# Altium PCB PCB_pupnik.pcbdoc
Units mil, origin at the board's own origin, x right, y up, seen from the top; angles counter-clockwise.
Board outline 4571.99 x 3535.82 mil, 4 copper layers (Top Layer, Inner1, Inner2, Bottom Layer); 78 components, 82 nets, 346 pads, 314 vias.
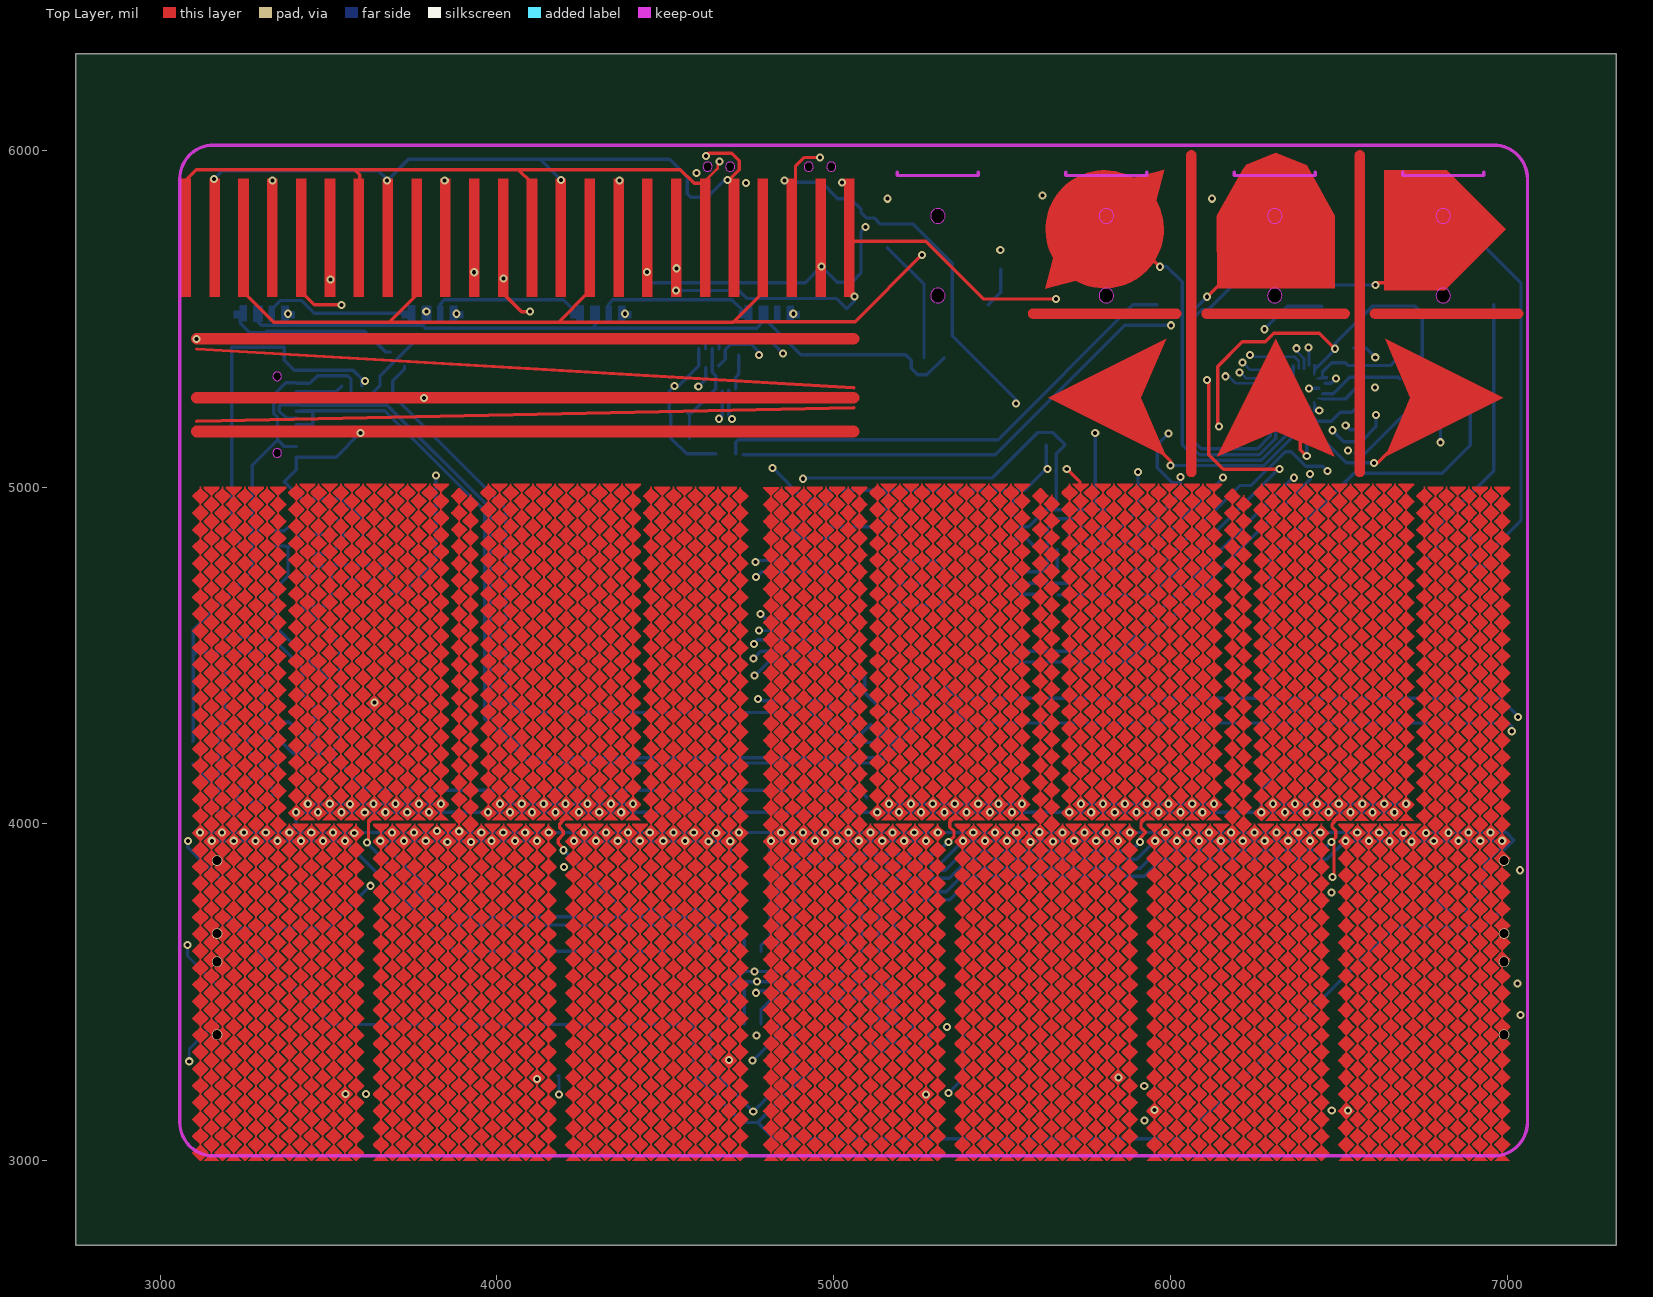
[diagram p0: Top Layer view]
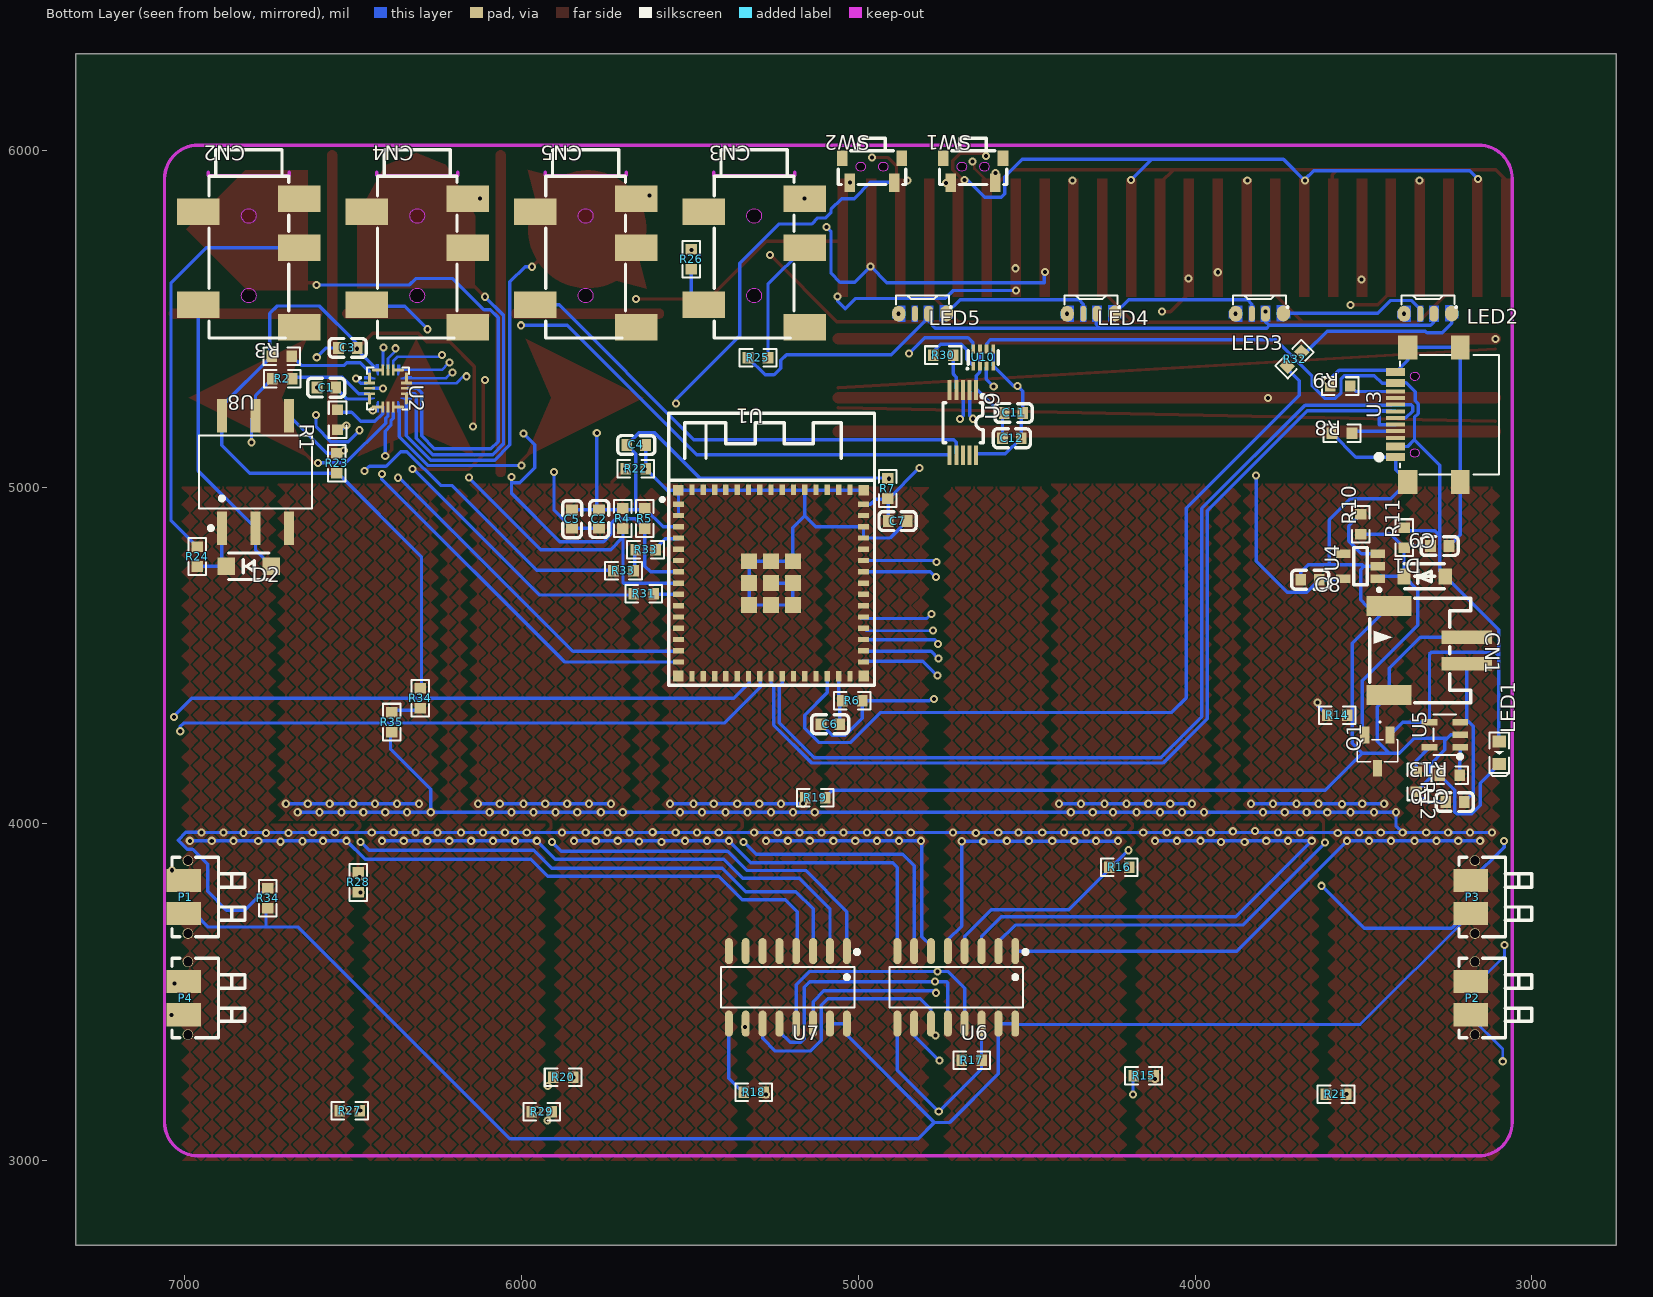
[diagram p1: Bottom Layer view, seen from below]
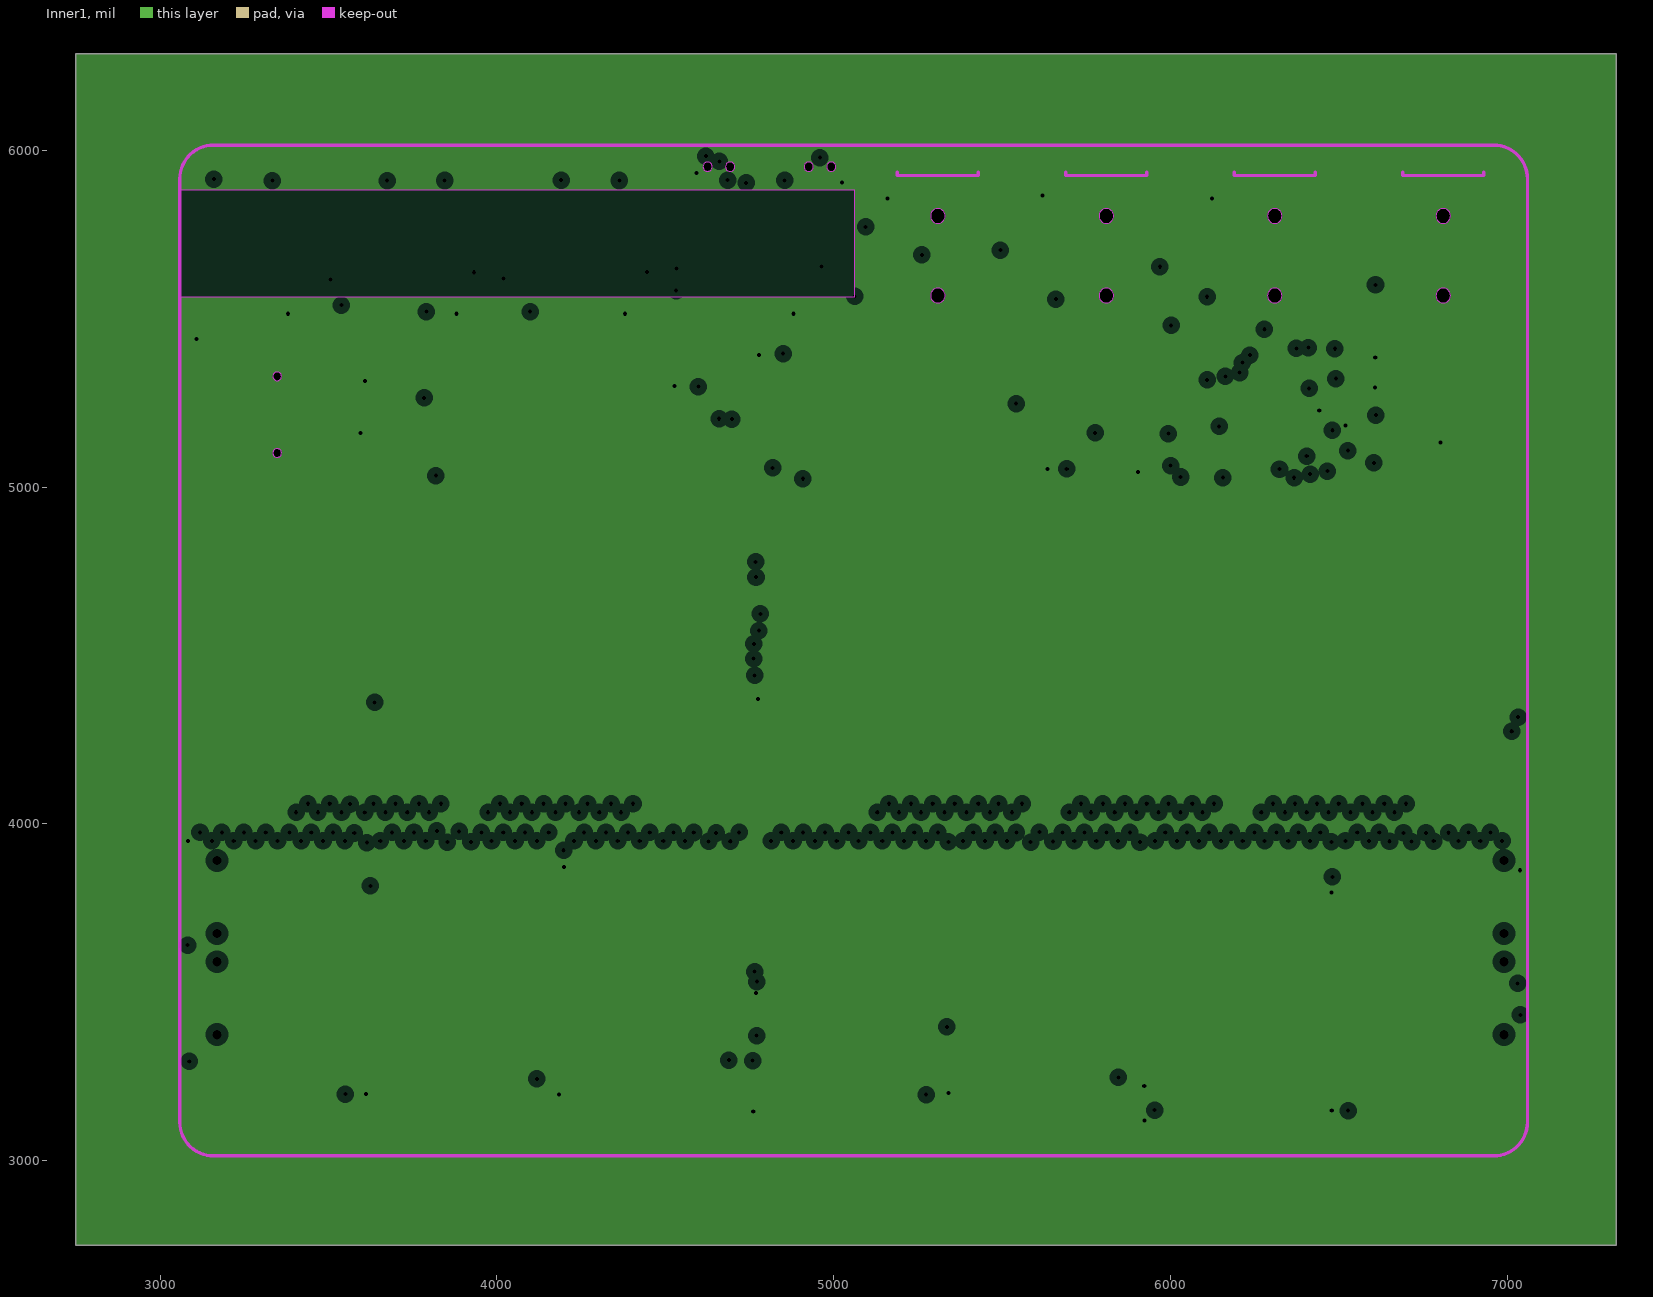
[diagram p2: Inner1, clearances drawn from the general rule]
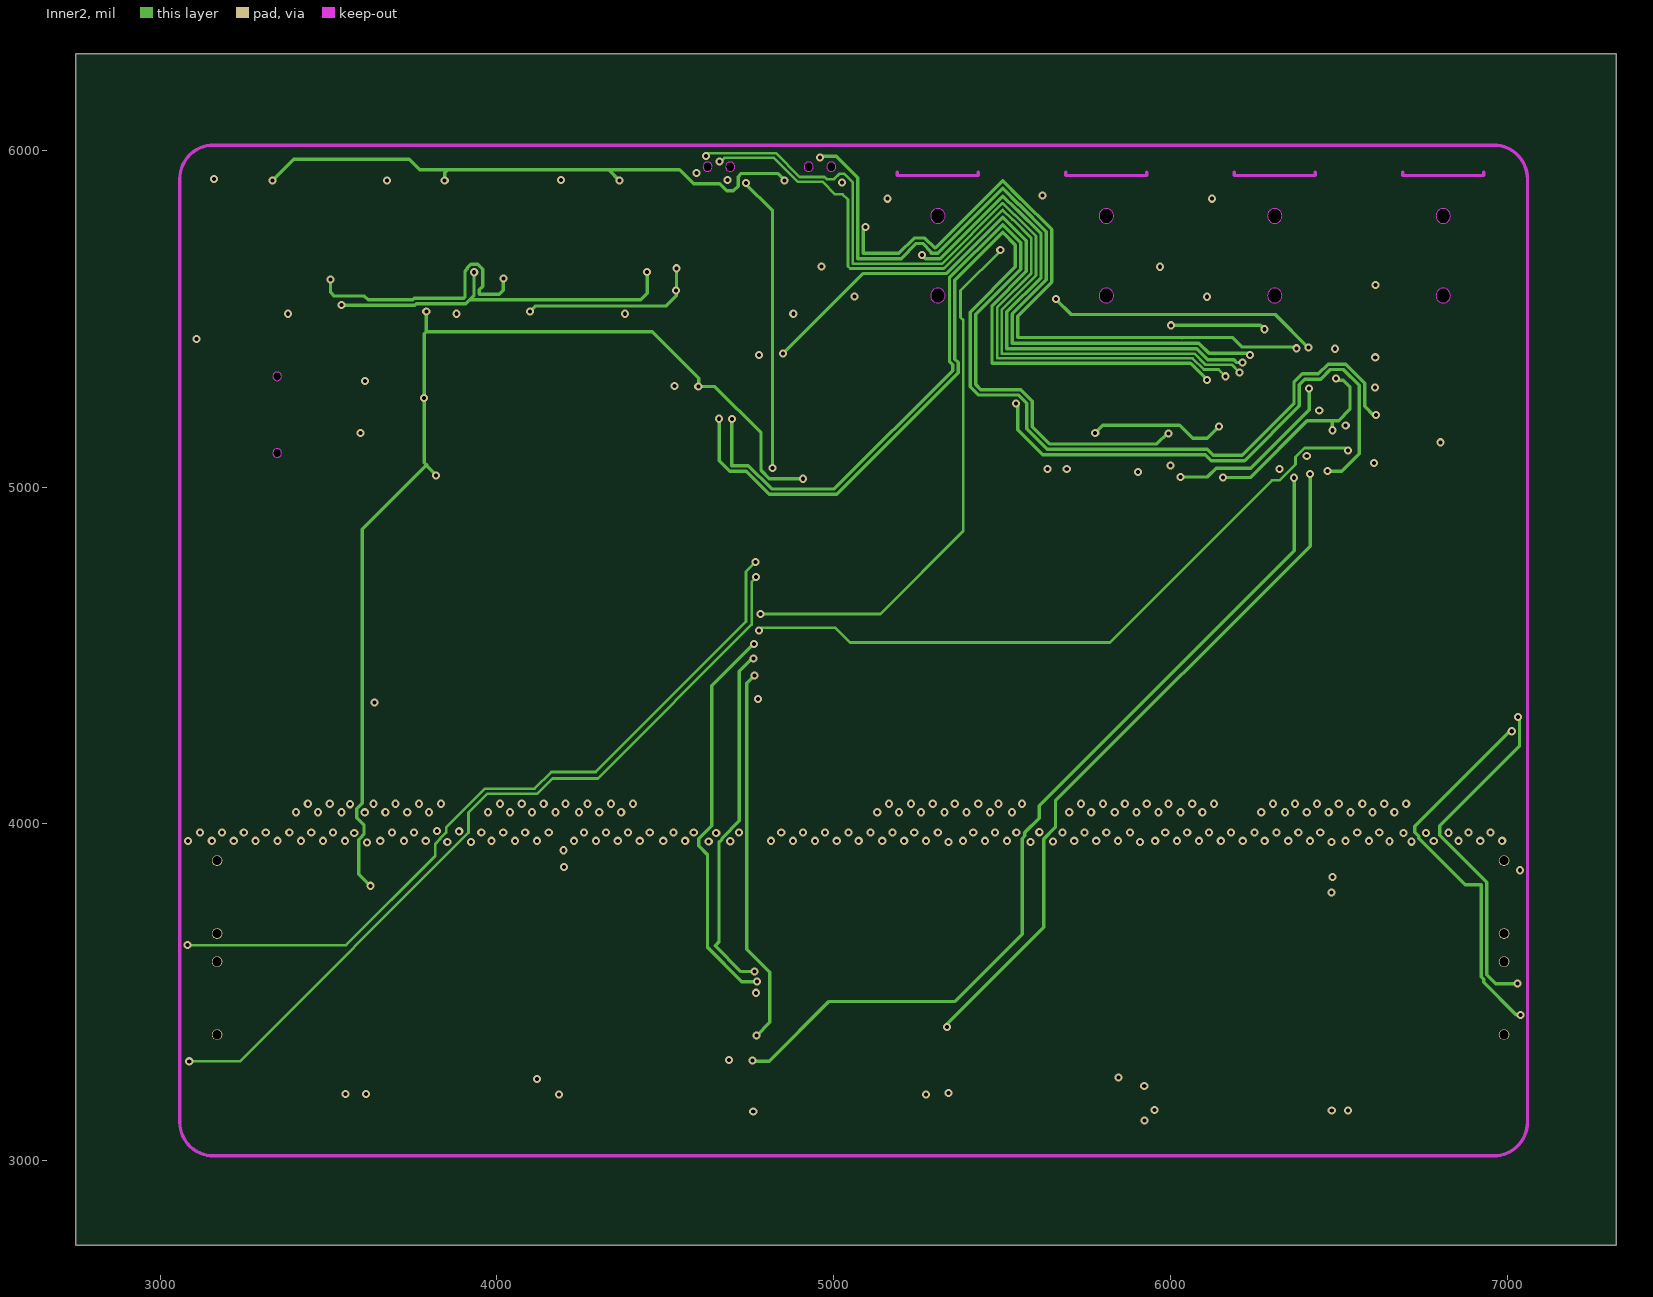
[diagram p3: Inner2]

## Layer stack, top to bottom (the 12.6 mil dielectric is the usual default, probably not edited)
Top Layer: signal copper (thickness not stored)
Dielectric: dielectric 12.6, FR-4, Dk 4.8
Inner1: plane copper (thickness not stored)
Dielectric: dielectric 12.6, FR-4, Dk 4.8
Inner2: signal copper (thickness not stored)
Dielectric: dielectric 12.6, FR-4, Dk 4.8
Bottom Layer: signal copper (thickness not stored)

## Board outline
7321.99,2750 2750,2750 2750,6285.82 7321.99,6285.82

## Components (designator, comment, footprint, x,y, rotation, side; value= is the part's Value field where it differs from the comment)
C1 "0.1u" C0603 6578.64,5294.85 r180 bottom
C2 "0.1u" C0603 5768.64,4904.85 r270 bottom
C3 "1u" C0603 6514.76,5412.85 r180 bottom
C4 "10u" C0603 5658.64,5124.85 r0 bottom
C5 "10u" C0603 5848.64,4904.85 r90 bottom
C6 "1u" C0603 5082.64,4295.85 r180 bottom
C7 "1u" C0603 4882.64,4898.85 r180 bottom
C8 "10u" C0603 3658.64,4724.85 r0 bottom
C9 "10u" C0603 3273.64,4824.85 r180 bottom
C10 "10u" C0603 3228.64,4064.85 r180 bottom
C11 "10u" C0603 4538.76,5219.85 r0 bottom
C12 "0.1u" C0603 4543.76,5144.85 r0 bottom
CN1 "BAT" CONN-SMD_P2.00_S2B-PH-SM4-TB-LF-SN 3308.64,4514.85 r270 bottom
CN2 "MIDI IN" AUDIO-SMD_PJ-327A5JJ 6808.64,5664.85 r180 bottom
CN3 "MIDI OUT" AUDIO-SMD_PJ-327A5JJ 5308.64,5664.85 r180 bottom
CN4 "CV" AUDIO-SMD_PJ-327A5JJ 6308.64,5664.85 r180 bottom
CN5 "GT" AUDIO-SMD_PJ-327A5JJ 5808.64,5664.85 r180 bottom
D1 "SM4007PL" SOD-123F_L2.8-W1.8-LS3.7-RD 3318.64,4734.85 r180 bottom
D2 "1N4148W" SOD-123FL_L2.6-W1.6-LS3.4-RD 6808.64,4764.85 r0 bottom
LED1 "LED-0603_R" LED0603_RED 3097.11,4211.38 r270 bottom
LED2 "SK6812SIDE-A-RVS" LED-SMD_4P-L4.0-W1.6-L 3308.64,5514.85 r0 bottom
LED3 "SK6812SIDE-A-RVS" LED-SMD_4P-L4.0-W1.6-L 3808.64,5514.85 r0 bottom
LED4 "SK6812SIDE-A-RVS" LED-SMD_4P-L4.0-W1.6-L 4308.64,5514.85 r0 bottom
LED5 "SK6812SIDE-A-RVS" LED-SMD_4P-L4.0-W1.6-L 4808.64,5514.85 r0 bottom
P1 "PogoPIN 2PIN 2.54mm" "POGOPIN 2PIN 2.5MM" 6898.64,3664.85 r270 bottom
P2 "PogoPIN 2PIN 2.54mm" "POGOPIN 2PIN 2.5MM" 3078.64,3364.85 r270 bottom
P3 "PogoPIN 2PIN 2.54mm" "POGOPIN 2PIN 2.5MM" 3078.64,3664.85 r270 bottom
P4 "PogoPIN 2PIN 2.54mm" "POGOPIN 2PIN 2.5MM" 6898.64,3364.85 r270 bottom
Q1 "DMG3415U-7" SOT-23-3_L2.9-W1.6-P1.90-LS2.8-BR-CW 3458.64,4214.85 r90 bottom
R1 "75k" R0603 6545.3,5199.51 r90 bottom
R2 "10k" R0603 6709.3,5321.51 r180 bottom
R3 "10k" R0603 6710.64,5388.85 r180 bottom
R4 "10k" R0603 5697.98,4906.51 r270 bottom
R5 "10k" R0603 5632.98,4906.51 r270 bottom
R6 "1M" R0603 5017.32,4365.85 r0 bottom
R7 "5.1k" R0603 4911.98,4995.51 r270 bottom
R8 "5.1k" R0603 3563.64,5159.85 r180 bottom
R9 "5.1k" R0603 3568.64,5299.85 r180 bottom
R10 "100k" R0603 3508.64,4889.85 r90 bottom
R11 "100k" R0603 3378.64,4849.85 r90 bottom
R12 "5.1k" R0603 3343.64,4124.85 r270 bottom
R13 "5.1k" R0603 3243.64,4144.85 r180 bottom
R14 "100K" R0603 3577.96,4322.85 r0 bottom
R15 "100K" R0603 4152.64,3252.85 r180 bottom
R16 "100K" R0603 4224.96,3871.85 r0 bottom
R17 "100K" R0603 4662.96,3298.85 r0 bottom
R18 "100K" R0603 5309.64,3203.85 r180 bottom
R19 "100K" R0603 5126.96,4077.85 r0 bottom
R20 "100K" R0603 5875.64,3247.85 r180 bottom
R21 "100K" R0603 3581.64,3197.85 r180 bottom
R22 "100K" R0603 5659.96,5053.85 r0 bottom
R23 "470" R0603 6546.98,5070.51 r270 bottom
R24 "220" R0603 6961.98,4793.51 r270 bottom
R25 "33" R0603 5297.32,5383.85 r0 bottom
R26 "10" R0603 5495.64,5675.85 r90 bottom
R27 "100K" R0603 6509.32,3148.85 r0 bottom
R28 "100K" R0603 6484.3,3826.51 r90 bottom
R29 "100K" R0603 5939.32,3145.85 r0 bottom
R30 "5.1k" R0603 4747.64,5391.85 r180 bottom
R31 "10k" R0603 5636.64,4682.85 r180 bottom
R32 "Res_0603" R0603 3704.64,5379.85 r315 bottom
R33 "Res_0603" R0603 5630.84,4813.97 r180 bottom
R33 "Res_0603" R0603 5696.48,4751.9 r180 bottom
R34 "Res_0603" R0603 6299.21,4372.78 r270 bottom
R34 "Res_0603" R0603 6752.83,3779.44 r90 bottom
R35 "Res_0603" R0603 6384.35,4302.22 r270 bottom
SW1 "RST" SW-SMD_L4.7-W3.5-P3.35-EH 4658.64,5939.85 r180 bottom
SW2 "BOOT" SW-SMD_L4.7-W3.5-P3.35-EH 4958.64,5939.85 r180 bottom
U1 "ESP32-S3-MINI-1-N8" BULETM-SMD_ESP32-S3-MINI-1-N8 5258.64,4714.85 r180 bottom
U2 "MPR121QR2" QFN-20_L3.0-W3.0-P0.40-BL 6395.64,5292.85 r270 bottom
U3 "GT-USB-9047A" USB-C-SMD_GT-USB-9047A 3308.64,5214.85 r90 bottom
U4 "AP2112K-3.3TRG1" SOT-25-5_L2.9-W1.6-P0.95-LS2.8-BL 3508.64,4764.85 r90 bottom
U5 "MCP73831T-2ACI/OT" SOT-23-5_L3.0-W1.7-P0.95-LS2.8-BL 3258.64,4264.85 r90 bottom
U6 "MCP3008-I/SL" SOIC-16_L9.9-W3.9-P1.27-LS6.0-BL 4708.64,3514.85 r0 bottom
U7 "MCP3008-I/SL" SOIC-16_L9.9-W3.9-P1.27-LS6.0-BL 5208.64,3514.85 r0 bottom
U8 "H11L1VSMT&amp;R" SMD-6_L8.6-W6.4-P2.54-LS9.4-BL 6788.64,5044.85 r180 bottom
U9 "MCP4728-E/UN" MSOP-10_L3.0-W3.0-P0.50-LS5.0-TL 4688.87,5191 r270 bottom
U10 "LM66200DRLR" SOT-583-8_L2.1-W1.2-P0.50-LS1.6-BL 4628.64,5384.85 r180 bottom

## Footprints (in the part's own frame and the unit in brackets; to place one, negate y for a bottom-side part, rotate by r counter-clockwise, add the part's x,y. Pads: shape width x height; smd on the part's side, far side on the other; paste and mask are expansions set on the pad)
AUDIO-SMD_PJ-327A5JJ [mm]
  rect 3.2x2 smd: 1(3.8,4.85) 2(-3.8,3.85) 3(3.8,1.15) 4(-3.8,-3.15) 5(3.8,-4.85)
  Board Outline Layer lines w0.254: 3.048,6.604 -3.048,6.604 ; 3.048,6.604 -3.048,6.604 ; 3.048,6.604 3.048,6.858 3.048,6.604 ; -3.048,6.604 -3.048,6.858 -3.048,6.604
  Multi-Layer board cut-out: -0.55,3.55 -0.496,3.789 -0.343,3.98 -0.123,4.086 0.122,4.086 0.343,3.98 0.495,3.789 0.55,3.55 0.55,3.55 0.495,3.311 0.343,3.12 0.122,3.014 -0.123,3.014 -0.343,3.12 -0.496,3.311 -0.55,3.55
  Multi-Layer board cut-out: -0.55,-2.45 -0.496,-2.211 -0.343,-2.02 -0.123,-1.914 0.122,-1.914 0.343,-2.02 0.495,-2.211 0.55,-2.45 0.55,-2.45 0.495,-2.689 0.343,-2.88 0.122,-2.986 -0.123,-2.986 -0.343,-2.88 -0.496,-2.689 -0.55,-2.45
  Multi-Layer keep-out region: -0.55,3.55 -0.496,3.789 -0.343,3.98 -0.123,4.086 0.122,4.086 0.343,3.98 0.495,3.789 0.55,3.55 0.55,3.55 0.495,3.311 0.343,3.12 0.122,3.014 -0.123,3.014 -0.343,3.12 -0.496,3.311 -0.55,3.55
  Multi-Layer keep-out region: -0.55,-2.45 -0.496,-2.211 -0.343,-2.02 -0.123,-1.914 0.122,-1.914 0.343,-2.02 0.495,-2.211 0.55,-2.45 0.55,-2.45 0.495,-2.689 0.343,-2.88 0.122,-2.986 -0.123,-2.986 -0.343,-2.88 -0.496,-2.689 -0.55,-2.45
  silkscreen extent -3,-5.65 3,8.55
BULETM-SMD_ESP32-S3-MINI-1-N8 [mm]
  rect 0.8x0.4 smd: 1(-6.975,5.95) 2(-6.975,5.1) 3(-6.975,4.25) 4(-6.975,3.4) 5(-6.975,2.55) 6(-6.975,1.7) 7(-6.975,0.85) 8(-6.975,0) 9(-6.975,-0.85) 10(-6.975,-1.7) 11(-6.975,-2.55) 12(-6.975,-3.4) 13(-6.975,-4.25) 14(-6.975,-5.1) 15(-6.975,-5.95) 31(6.975,-5.95) 32(6.975,-5.1) 33(6.975,-4.25) 34(6.975,-3.4) 35(6.975,-2.55) 36(6.975,-1.7) 37(6.975,-0.85) 38(6.975,0) 39(6.975,0.85) 40(6.975,1.7) 41(6.975,2.55) 42(6.975,3.4) 43(6.975,4.25) 44(6.975,5.1) 45(6.975,5.95)
  rect 0.4x0.8 smd: 16(-5.95,-7.025) 17(-5.1,-7.025) 18(-4.25,-7.025) 19(-3.4,-7.025) 20(-2.55,-7.025) 21(-1.7,-7.025) 22(-0.85,-7.025) 23(0,-7.025) 24(0.85,-7.025) 25(1.7,-7.025) 26(2.55,-7.025) 27(3.4,-7.025) 28(4.25,-7.025) 29(5.1,-7.025) 30(5.95,-7.025) 46(5.95,7.025) 47(5.1,7.025) 48(4.25,7.025) 49(3.4,7.025) 50(2.55,7.025) 51(1.7,7.025) 52(0.85,7.025) 53(0,7.025) 54(-0.85,7.025) 55(-1.7,7.025) 56(-2.55,7.025) 57(-3.4,7.025) 58(-4.25,7.025) 59(-5.1,7.025) 60(-5.95,7.025)
  rect 0.8x0.8 smd: 61(7,7) 62(-7,-7) 63(7,-7) GND(-7,7)
  rect 1.2x1.2 smd: 64(-1.65,1.65) 65(0,1.65) 66(1.65,1.65) 67(-1.65,0) 68(0,0) 69(1.65,0) 70(-1.65,-1.65) 71(0,-1.65) 72(1.65,-1.65)
  silkscreen extent -8.34,-7.7 7.8,12.8
C0603 [mm]
  rect 0.8x0.9 smd: 1(-0.7,0) 2(0.7,0)
  silkscreen extent -1.41,-0.71 1.39,0.72
CONN-SMD_P2.00_S2B-PH-SM4-TB-LF-SN [mm]
  rect 1x3.8 smd: 1(-1,2.925) 2(1,2.925)
  rect 1.5x3.4 smd: 3(3.35,-2.925) 4(-3.35,-2.925)
  silkscreen extent -3.95,-4.37 3.95,3.22
LED0603_RED [mm]
  rect 0.9x1 smd: 1(-0.85,0) 2(0.85,0)
  silkscreen extent -1.54,-0.73 1.75,0.73
LED-SMD_4P-L4.0-W1.6-L [mm]
  oval 1x1.2 smd: 1(-1.8,-0.012) 4(1.8,0.013)
  oval 0.7x1.2 smd: 2(-0.45,0.013)
  oval 0.45x1.2 smd: 3(0.575,0.013)
  Top Layer region: 1.3,0.612 1.3,-0.588 1.85,-0.587 1.85,-0.188 2.3,-0.188 2.3,0.362 1.85,0.362 1.85,0.612
  Top Layer region: 0.35,-0.588 0.8,-0.588 0.8,0.612 0.35,0.612
  Top Layer region: -0.8,0.613 -0.8,-0.587 -0.1,-0.587 -0.1,0.613
  Top Layer region: -1.3,0.588 -1.3,-0.612 -1.85,-0.612 -1.85,-0.212 -2.3,-0.212 -2.3,0.338 -1.85,0.338 -1.85,0.588
  silkscreen extent -2.2,-1.36 2,-0.41
MSOP-10_L3.0-W3.0-P0.50-LS5.0-TL [mil]
  rect 59.05x12 smd: 1(-96.5,39.37) 2(-96.5,19.68) 3(-96.5,0) 4(-96.5,-19.69) 5(-96.5,-39.37) 6(96.5,-39.37) 7(96.5,-19.69) 8(96.5,0) 9(96.5,19.68) 10(96.5,39.37)
  silkscreen extent -84,-59 59,64
"POGOPIN 2PIN 2.5MM" [mm]
  rect 1.75x2.6 smd: 1(-4.25,-2.6) 2(-1.75,-2.6)
  round 0.8 hole 0.7: 3(-5.75,-2.3) 4(-0.25,-2.3)
  silkscreen extent -6,-3.5 0,2
QFN-20_L3.0-W3.0-P0.40-BL [mm]
  oval 0.825x0.224 smd: 1(-0.8,-1.388) 5(0.8,-1.388) 11(0.8,1.388) 15(-0.8,1.388)
  rect 0.2x0.825 smd: 2(-0.4,-1.388) 3(0,-1.388) 4(0.4,-1.388) 12(0.4,1.388) 13(0,1.388) 14(-0.4,1.388)
  oval 0.224x0.825 smd: 6(1.388,-0.8) 10(1.388,0.8) 16(-1.387,0.8) 20(-1.388,-0.8)
  rect 0.825x0.2 smd: 7(1.388,-0.4) 8(1.388,0) 9(1.388,0.4) 17(-1.387,0.4) 18(-1.387,0) 19(-1.387,-0.4)
  Top Layer region: 0.688,-1.8 0.688,-0.975 0.8,-0.975 0.912,-1.388 0.912,-1.8
  Top Layer region: -1.8,-0.688 -0.975,-0.688 -0.975,-0.8 -1.388,-0.912 -1.8,-0.912
  Top Layer region: -0.688,1.8 -0.688,0.975 -0.8,0.975 -0.912,1.388 -0.912,1.8
  Top Layer region: 1.8,0.688 0.975,0.688 0.975,0.8 1.388,0.912 1.8,0.912
  Top Layer region: 1.8,-0.688 0.975,-0.688 0.975,-0.8 1.388,-0.912 1.8,-0.912
  Top Layer region: 0.688,1.8 0.688,0.975 0.8,0.975 0.912,1.388 0.912,1.8
  Top Layer region: -1.8,0.688 -0.975,0.688 -0.975,0.8 -1.387,0.912 -1.8,0.912
  Top Layer region: -0.688,-1.8 -0.688,-0.975 -0.8,-0.975 -0.912,-1.388 -0.912,-1.8
  silkscreen extent -1.58,-2.18 1.58,1.58
R0603 [mil]
  rect 31.75x34.02 smd: 1(-29.66,0) 2(29.66,0)
  silkscreen extent -55,-26 55,26
SMD-6_L8.6-W6.4-P2.54-LS9.4-BL [mil]
  rect 29.76x99.37 smd: 1(-100,-166.81) 2(0,-166.81) 3(100,-166.81) 4(100,166.81) 5(0,166.81) 6(-100,166.81)
  silkscreen extent -168,-173 168,108
SOD-123F_L2.8-W1.8-LS3.7-RD [mm]
  rect 1x1.2 smd: 1(-1.55,0) 2(1.55,0)
  silkscreen extent -1.52,-0.93 1.49,0.95
SOD-123FL_L2.6-W1.6-LS3.4-RD [mm]
  rect 1.3x1.3 smd: 1(1.7,0) 2(-1.7,0)
  silkscreen extent -1.5,-1 1.5,1
SOIC-16_L9.9-W3.9-P1.27-LS6.0-BL [mil]
  oval 23.7x77.6 smd: 1(-175,-107.7) 2(-125,-107.7) 3(-75,-107.7) 4(-25,-107.7) 5(25,-107.7) 6(75,-107.7) 7(125,-107.7) 8(175,-107.7) 9(175,107.7) 10(125,107.7) 11(75,107.7) 12(25,107.7) 13(-25,107.7) 14(-75,107.7) 15(-125,107.7) 16(-175,107.7)
  silkscreen extent -211,-111 198,60
SOT-23-3_L2.9-W1.6-P1.90-LS2.8-BR-CW [mm]
  rect 1.25x0.7 smd: 1(1.25,-0.95) 2(-1.25,0) 3(1.25,0.95)
  silkscreen extent -0.76,-1.52 2.28,1.52
SOT-23-5_L3.0-W1.7-P0.95-LS2.8-BL [mm]
  rect 0.49x1.157 smd: 1(-0.95,-1.154) 2(0,-1.154) 3(0.95,-1.154)
  rect 0.49x1.175 smd: 4(0.95,1.154) 5(-0.95,1.154)
  silkscreen extent -1.8,-1.29 1.53,0.85
SOT-25-5_L2.9-W1.6-P0.95-LS2.8-BL [mil]
  rect 24.5x43.5 smd: 1(-37.39,-51.18) 2(-0.03,-51.18) 3(37.39,-51.18) 4(37.39,51.18) 5(-37.39,51.18)
  silkscreen extent -75,-60 56,20
SOT-583-8_L2.1-W1.2-P0.50-LS1.6-BL [mm]
  rect 0.28x0.68 smd: 1(-0.75,-0.64) 2(-0.25,-0.64) 3(0.25,-0.64) 4(0.75,-0.64) 5(0.75,0.64) 6(0.25,0.64) 7(-0.25,0.64) 8(-0.75,0.64)
  silkscreen extent -1.27,-0.93 1.14,0.51
SW-SMD_L4.7-W3.5-P3.35-EH [mm]
  rect 0.8x1.4 smd: 1(-1.675,-0.917) 2(1.675,-0.917)
  rect 0.8x1.2 smd: 3(-2.25,0.917) 4(2.25,0.917)
  Multi-Layer board cut-out: -1.2,0.282 -1.165,0.434 -1.068,0.556 -0.928,0.624 -0.772,0.624 -0.632,0.556 -0.535,0.434 -0.5,0.282 -0.5,0.282 -0.535,0.131 -0.632,0.009 -0.772,-0.059 -0.928,-0.059 -1.068,0.009 -1.165,0.131 -1.2,0.282
  Multi-Layer board cut-out: 0.5,0.282 0.535,0.434 0.632,0.556 0.772,0.624 0.928,0.624 1.068,0.556 1.165,0.434 1.2,0.282 1.2,0.282 1.165,0.131 1.068,0.009 0.928,-0.059 0.772,-0.059 0.632,0.009 0.535,0.131 0.5,0.282
  Multi-Layer keep-out region: -1.2,0.282 -1.165,0.434 -1.068,0.556 -0.928,0.624 -0.772,0.624 -0.632,0.556 -0.535,0.434 -0.5,0.282 -0.5,0.282 -0.535,0.131 -0.632,0.009 -0.772,-0.059 -0.928,-0.059 -1.068,0.009 -1.165,0.131 -1.2,0.282
  Multi-Layer keep-out region: 0.5,0.282 0.535,0.434 0.632,0.556 0.772,0.624 0.928,0.624 1.068,0.556 1.165,0.434 1.2,0.282 1.2,0.282 1.165,0.131 1.068,0.009 0.928,-0.059 0.772,-0.059 0.632,0.009 0.535,0.131 0.5,0.282
  silkscreen extent -2.54,-1.07 2.54,2.43
USB-C-SMD_GT-USB-9047A [mm]
  rect 1.8x1.45 smd: 12(-5.07,1.524) 13(5.07,1.524)
  rect 1.8x1.4 smd: 14(-5.07,-2.436) 15(5.07,-2.436)
  rect 0.6x1.45 smd: A1B12(-3.2,2.437) A4B9(-2.4,2.437) A9B4(2.4,2.437) A12B1(3.2,2.437)
  rect 0.3x1.45 smd: A5(-1.25,2.437) A6(-0.25,2.437) A7(0.25,2.437) A8(1.25,2.437) B5(1.75,2.437) B6(0.75,2.437) B7(-0.75,2.437) B8(-1.75,2.437)
  Multi-Layer board cut-out: 2.89,1.319 3.031,1.286 3.144,1.196 3.207,1.066 3.207,0.921 3.144,0.791 3.031,0.701 2.89,0.669 2.89,0.669 2.749,0.701 2.636,0.791 2.573,0.921 2.573,1.066 2.636,1.196 2.749,1.286 2.89,1.319
  Multi-Layer board cut-out: -2.89,1.318 -2.749,1.286 -2.636,1.196 -2.573,1.065 -2.573,0.921 -2.636,0.791 -2.749,0.7 -2.89,0.668 -2.89,0.668 -3.031,0.7 -3.144,0.791 -3.207,0.921 -3.207,1.065 -3.144,1.196 -3.031,1.286 -2.89,1.318
  Multi-Layer keep-out region: 2.89,1.319 3.031,1.286 3.144,1.196 3.207,1.066 3.207,0.921 3.144,0.791 3.031,0.701 2.89,0.669 2.89,0.669 2.749,0.701 2.636,0.791 2.573,0.921 2.573,1.066 2.636,1.196 2.749,1.286 2.89,1.319
  Multi-Layer keep-out region: -2.89,1.318 -2.749,1.286 -2.636,1.196 -2.573,1.065 -2.573,0.921 -2.636,0.791 -2.749,0.7 -2.89,0.668 -2.89,0.668 -3.031,0.7 -3.144,0.791 -3.207,0.921 -3.207,1.065 -3.144,1.196 -3.031,1.286 -2.89,1.318
  silkscreen extent -4.5,-5.36 4.5,3.89

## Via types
v1: diameter 24.41, hole 12.2, Top Layer to Bottom Layer, 180 vias
v2: diameter 24, hole 12, Top Layer to Bottom Layer, 134 vias

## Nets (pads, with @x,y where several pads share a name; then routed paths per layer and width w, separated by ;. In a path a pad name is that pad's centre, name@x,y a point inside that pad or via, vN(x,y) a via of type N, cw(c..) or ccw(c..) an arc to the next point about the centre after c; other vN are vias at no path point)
3V3: C2.1 C3.2 C4.2 C5.2 C8.1 LED2.2 LED3.2 LED4.2 LED5.2 P1.2 P3.2 R3.1 R4.1 R5.1 R7.1 R23.2 R25.2 R34.1 U1.3 U2.20 U4.5 U6.15 U6.16 U7.15 U7.16 U8.6 U10.3 | length 18170.9
  Top Layer w10: v2(6143.62,5179.75) 6138.89,5184.49 6138.89,5357.78 6212.16,5431.05 6280.09,5431.05 6305.28,5456.24 6441.14,5456.24 v2(6486.93,5410.44)
  Top Layer w35: 3108.64,5264.85 v2(3783.64,5264.85) 5058.64,5264.85
  Inner2 w10: v2(3624.18,3816.46) 3589.93,3850.7 3589.93,3953.33 3595.22,3958.62 3595.22,3959.28 3605.22,3969.28 3605.22,3997.08 3583.43,4018.86 3583.43,4045.4 3599.71,4061.69 3599.71,4874.35 3790.21,5064.84 ; v2(3790.21,5520.76) 3790.21,5461.17 ; 3791.64,5066.28 3790.21,5064.84 ; v2@3818.64,5036.29 3790.21,5064.72 3790.21,5064.84 ; v2(4597.56,5298.34) v2@4599.13,5298.34 ; v2@4599.13,5297.9 v2@4599.13,5298.34 ; v2(4908.29,5024.65) 4808.31,5024.65 4783.88,5049.08 4783.88,5161.27 4646.82,5298.34 v2@4599.13,5298.34 ; v2(5775.74,5160.92) 5798.38,5183.56 6026.08,5183.56 6065.01,5144.64 6108.52,5144.64 v2(6143.62,5179.75) ; 3790.21,5064.84 3783.64,5071.41 v2(3783.64,5264.85) 3783.64,5454.6 3790.21,5461.17 ; 3790.21,5461.17 4460.77,5461.17 4599.13,5322.81 v2@4599.13,5298.34
  Bottom Layer w8: P3.2@3185.96,3728.55 3509.96,3404.55 U6.16@4535.77,3404.55
  Bottom Layer w10: P3.2@3182.46,3729.4 3199.2,3729.4 3238.64,3689.95 3497.67,3689.95 v2@3622.99,3815.27 ; LED2.2 3290.93,5489.74 3300.93,5479.74 3779.75,5479.74 ; U4.5 3562.43,4724.85 C8.1 3668.45,4687.48 3726.28,4687.48 3818.64,4779.83 v2(3818.64,5034) ; LED3.2 3790.93,5490.91 3779.75,5479.74 ; LED4.2 4293.64,5511.64 4293.64,5482.85 4282.64,5471.85 ; U6.16 U6.15 4583.64,3258.85 4728.64,3113.85 4773.64,3113.85 ; v2(4597.56,5298.34) 4619.79,5320.57 U10.3@4619.79,5354.77 ; LED5.2 LED5.2@4790.93,5503.56 ; R7.1 4913.66,5026.85 5470.64,5026.85 5605.64,5161.85 5649.2,5161.85 C4.2 5660.33,5098.98 5660.33,4932.41 ; U7.15 U7.16 5033.64,3373.85 4773.64,3113.85 ; R25.2 5275.98,5332.85 5249.64,5332.85 5229.64,5352.85 5229.64,5375.85 5212.64,5392.85 4901.64,5392.85 LED5.2@4790.93,5503.56 ; U1.3 5578.99,4882.18 R5.1 5636.74,4932.41 5660.33,4932.41 ; C2.1@5769.63,4938.05 5775.74,4944.15 v2(5775.74,5160.92) ; C5.2 C2.1 5660.33,4932.41 ; R34.1@6296.18,4401.17 6296.18,4793.68 R23.2@6542.71,5040.21 ; U2.20 6487.2,5407.54 C3.2 ; C3.2@6488.65,5415.98 6488.65,5426.67 6599.32,5537.34 6724.49,5537.34 6746.63,5515.2 R3.1@6746.63,5386.21 ; R23.2 6805.64,5040.85 6888.64,5123.85 U8.6 6888.64,5240.51 R3.1 ; R34.1@6757.41,3747.38 6757.41,3696.5 6757.92,3695.99 ; P1.2@6985.01,3733.41 6968.28,3733.41 6928.83,3693.96 6661.63,3693.96 6033.62,3065.95 4821.54,3065.95 4773.64,3113.85 ; 3779.75,5479.74 3787.64,5471.85 4282.64,5471.85 ; 4282.64,5471.85 4770.64,5471.85 4790.93,5492.14 LED5.2@4790.93,5503.56
$1N143: R1.2 U2.7 | length 178.1
  Bottom Layer w10: U2.7 6411.39,5217.76 6434.3,5194.85 6476.64,5194.85 6503.64,5221.85 6537.98,5221.85 R1.2
$1N157: R2.2 U2.4 | length 251.3
  Bottom Layer w10: U2.4@6450.27,5277.34 6482.13,5277.34 6530.64,5325.85 6675.3,5325.85 R2.2
$1N175: R3.2 U2.1 | length 274.1
  Bottom Layer w10: U2.1 6450.27,5341.48 6477.64,5368.85 6517.64,5368.85 6525.64,5360.85 6652.98,5360.85 R3.2
$1N193: C1.2 U2.5 | length 114.7
  Bottom Layer w10: U2.5 6517.57,5261.34 C1.2
$1N354: C6.2 R6.2 U1.29 | length 150.3
  Bottom Layer w10: C6.2 5055.08,4357.75 R6.2 5057.85,4376.72 U1.29
$1N512: C9.1 D1.1 Q1.3 R10.1 R11.1 U4.1 | length 951.8
  Bottom Layer w10: C9.1 3373.98,4824.85 R11.1 ; U4.1 3450.07,4734.85 D1.1 ; Q1.3 3503.64,4271.65 3503.64,4424.85 3338.64,4589.85 3338.64,4693.83 D1.1 ; R10.1 3418.64,4860.19 R11.1 ; R11.1 3379.66,4819.17 D1.1
$1N704: C10.2 CN1.2 U5.3 | length 457.4
  Bottom Layer w10: CN1.2 3193.48,4309.69 3186.04,4302.25 ; C10.2 3173.64,4092.29 3173.64,4289.85 3186.04,4302.25 ; U5.3 3186.04,4302.25
$1N1108: LED2.3 LED3.1 | length 446.5
  Bottom Layer w10: LED2.3 3331.28,5527.49 3357.64,5553.85 3419.64,5553.85 3458.15,5515.34 LED3.1
$1N1109: LED3.3 LED4.1 | length 457.2
  Bottom Layer w10: LED3.3 3831.28,5542.97 3844.16,5555.85 4197.27,5555.85 LED4.1
$1N1133: LED4.3 LED5.1 | length 457.2
  Bottom Layer w10: LED4.3 4331.28,5542.97 4344.16,5555.85 4697.27,5555.85 LED5.1
$1N1275: CN2.4 D2.2 U8.2 | length 865.7
  Bottom Layer w10: D2.2 6788.64,4811.78 U8.2 6958.24,5047.64 CN2.4
$1N1289: CN2.3 R24.1 | length 1238.1
  Bottom Layer w10: CN2.3 6934.37,5710.12 7039.64,5604.85 7039.64,4900.83 R24.1
$1N1451: C11.2 C12.2 U9.1 U10.2 U10.7 | length 312.8
  Bottom Layer w10: C12.2 4571.32,5214.85 C11.2 4577.77,5219.85 4649.27,5291.35 4649.27,5330.47 4638.48,5341.26 U10.2 U10.7
$1N1517: CN4.4 U9.6 | length 1910.6
  Inner2 w10: v2(6001.23,5480.11) 6266.34,5480.11 v2(6278.04,5468.41)
  Bottom Layer w10: U9.6@4730.54,5095.88 5478.85,5095.88 5863.09,5480.11 v2(6001.23,5480.11) ; v2(6278.04,5468.41) 6345.97,5536.34 CN4.4@6449.01,5536.34
$1N1518: CN5.4 U9.7 | length 1453.4
  Bottom Layer w10: U9.7@4708.33,5098.35 4708.33,5132.88 4716.3,5140.85 5487.64,5140.85 5887.62,5540.83 CN5.4
$1N1636: R8.2 U3.A5 | length 131.8
  Bottom Layer w10: U3.A5 3528.19,5165.64 R8.2
$1N1637: R9.2 U3.B5 | length 141.1
  Bottom Layer w10: U3.B5@3404.57,5283.75 3522.89,5283.75 R9.2
$1N1644: R10.2 U4.3 | length 195.9
  Bottom Layer w10: U4.3 3506.03,4802.24 3543.64,4839.85 3543.64,4884.51 R10.2
$1N1651: R13.2 U5.1 | length 82.6
  Bottom Layer w10: U5.1 R13.2@3213.94,4144.85
$1N1656: R12.1 U5.5 | length 89.3
  Bottom Layer w10: U5.5 3343.64,4187.87 R12.1
$1N1659: LED1.2 R13.1 | length 362.4
  Bottom Layer w10: LED1.2 3153.64,4121.39 3153.64,4054.85 3178.64,4029.85 3223.64,4029.85 3228.64,4034.85 3228.64,4100.19 R13.1
$1N1720: D2.1 R24.2 U8.1 | length 205.4
  Bottom Layer w10: U8.1 6888.64,4777.92 D2.1 6960.98,4764.85 R24.2
$1N1727: CN3.4 R26.1 | length 120.9
  Bottom Layer w10: CN3.4 5495.64,5578.23 R26.1
$1N1728: CN3.3 R25.1 | length 371.3
  Bottom Layer w10: CN3.3 5267.66,5601.5 R25.1
$1N1745: R30.2 U9.4 | length 104.5
  Bottom Layer w10: U9.4@4708.33,5291.35 4708.33,5325.88 4717.98,5335.53 R30.2
$1N1760: R31.1 U10.8 | length 3476.2
  Top Layer w10: v2@6108.16,5320.05 6113.12,5315.09 6113.12,5096.29 6156.43,5052.98 v2(6322.72,5052.98)
  Inner2 w10: v2@4850.38,5397.71 5086.33,5633.67 5333.29,5633.67 5501.1,5801.47 5570.88,5731.69 5570.88,5639.92 5469.51,5538.56 5469.51,5366.93 6058.68,5366.93 v2(6107.59,5318.02)
  Bottom Layer w10: U10.8@4659.06,5409.93 4659.06,5428.31 4673.75,5443 4802.55,5443 v2(4849.36,5396.19) ; R31.1@5666.2,4679.47 5945.63,4679.47 v2@6318.65,5052.49
A_SIG: R29.2 U7.2 | length 1539
  Bottom Layer w10: U7.2 5083.64,3747.85 5174.64,3838.85 5342.64,3838.85 5398.64,3894.85 5898.64,3894.85 v1(5953.64,3949.85) v1(6413.64,3949.85)
  other v1: 6018.64,3949.85 6083.64,3949.85 6148.64,3949.85 6213.64,3949.85 6278.64,3949.85 6348.64,3949.85
  other v2: 5951.8,3150.39
ADC-CS-0: U1.14 U6.10 | length 3835.1
  Inner2 w10: v2@4758.2,3295.42 4807.81,3295.42 4985.55,3473.16 5359.59,3473.16 5558.8,3672.37 5558.8,3956.6 5566.81,3964.61 5566.81,3974.61 5609.17,4016.97 5609.17,4053.61 6366.11,4810.55 v2(6366.11,5027.59)
  Bottom Layer w10: v2(4758.88,3297.45) 4833.05,3371.63 U6.10@4833.05,3403.29 ; U1.14@5529.24,4512.35 5846.37,4512.35 v2@6366.15,5032.13
ADC-CS-1: U1.15 U7.10 | length 3208.8
  Inner2 w10: v2@5333.85,3394.96 5333.85,3403.71 5622.97,3692.84 5622.97,3955.27 5657.76,3990.06 5657.76,4068.49 6413.76,4824.48 v2(6413.76,5038.22)
  Bottom Layer w10: U1.15@5533.36,4480.68 5870.8,4480.68 6414.83,5024.71 v2@6414.83,5036.1
  other v2: 5335.43,3397.68
AS_SIG: R28.2 U7.3 | length 2136.4
  Top Layer w10: v2(6479.64,3842.85) 6484.64,3847.85 6484.64,3938.85 v2(6476.64,3946.85) 6476.64,3947.85 6489.64,3960.85 6489.64,3979.85 6478.64,3990.85 6478.64,3999.85 6491.64,4012.85
  Bottom Layer w10: U7.3 5133.64,3747.85 5184.64,3798.85 5333.64,3798.85 5403.64,3868.85 5909.64,3868.85 5962.64,3921.85 6451.64,3921.85 v2(6476.64,3946.85) ; v1(6303.64,4059.85) v1(6698.64,4059.85)
  other v1: 6368.64,4059.85 6433.64,4059.85 6498.64,4059.85 6568.64,4059.85 6633.64,4059.85
B0: R33.2@5601.18,4813.97 U1.4 | length 78.7
  Bottom Layer w10: U1.4@5532.81,4846.15 5572.16,4846.15 R33.2@5599.97,4818.33
B1: R33.1@5660.5,4813.97 R33.2@5666.82,4751.9 | length 66.5
  Bottom Layer w10: R33.1@5662.84,4813.47 5662.84,4749.36 R33.2@5664.54,4747.66
B_SIG: R27.2 U7.4 | length 2008.5
  Bottom Layer w10: U7.4 5180.64,3625.55 5180.64,3739.85 5215.64,3774.85 5343.64,3774.85 5413.64,3844.85 5921.64,3844.85 5971.64,3894.85 6463.64,3894.85 v1(6518.64,3949.85) v1(6983.64,3949.85)
  other v1: 6714.72,3947.44 6649.34,3948.72 6780.47,3949.1 6588.64,3949.85 6853.64,3949.85 6918.64,3949.85
  other v2: 6526.1,3148.85
BOOT: R33.1@5726.14,4751.9 SW2.2 | length 3585.7
  Inner2 w10: v2@5540.34,5246.29 5545.68,5240.95 5545.68,5169.97 5619.71,5095.93 6102.09,5095.93 6119.65,5078.38 6219,5078.38 6381.65,5241.04 6381.65,5304.13 6397.43,5319.91 6444.75,5319.91 6473.75,5348.91 6512.43,5348.91 6559.75,5301.59 6559.75,5099.07 6508.01,5047.33 v2(6464.87,5047.33)
  Bottom Layer w10: SW2.2@4891.24,5904.3 4963.56,5904.3 5011.9,5855.96 5048.54,5855.96 5080.59,5823.9 5080.59,5813.9 5095.75,5798.74 5120.12,5798.74 5138.21,5780.65 5235.79,5780.65 5351.8,5664.64 5351.8,5448.64 5541.09,5259.35 v2@5541.09,5247.9 ; R33.1@5727.55,4753.26 5954.49,4753.26 6205.86,5004.62 6239.04,5004.62 6339.42,5105 6357.97,5105 6401.21,5061.75 6450.45,5061.75 v2(6464.87,5047.33)
  other v2: 5540.87,5247.57
C_SIG: R21.2 U6.1 | length 1515.6
  Bottom Layer w10: v1(3153.64,3949.85) v1(3548.64,3949.85) 3875.94,3622.55 U6.1
  other v1: 3218.64,3949.85 3283.64,3949.85 3348.64,3949.85 3418.64,3949.85 3483.64,3949.85
  other v2: 3550.34,3197.85
CAP0: U2.8 | length 349.9
  Top Layer w10: v2(6602.64,5071.85) 6614.64,5071.85 6650.64,5107.85
  Bottom Layer w10: U2.8@6395.39,5224.85 6395.39,5211.13 6402.64,5203.88 6402.64,5189.74 6520.53,5071.85 v2(6602.64,5071.85)
CAP1: U2.9 | length 195.2
  Top Layer w10: 6384.64,5140.85 6384.64,5110.85 v2(6403.64,5091.85)
  Bottom Layer w10: 6379.39,5220.09 6379.39,5204.5 6386.64,5197.25 6386.64,5183.11 6403.64,5166.11 v2(6403.64,5091.85)
CAP2: U2.10 | length 539.6
  Top Layer w10: 5971.64,5104.85 5999.64,5076.85 v2(5999.64,5063.85)
  Bottom Layer w10: v2(5999.64,5063.85) 6275.64,5063.85 6361.64,5149.85 6361.64,5235.71 U2.10
CAP3: U2.11 | length 1071.8
  Top Layer w10: 5937.64,5672.85 5948.64,5672.85 v2(5967.64,5653.85)
  Bottom Layer w10: v2(5967.64,5653.85) 5988.64,5653.85 6033.64,5608.85 6033.64,5124.85 6078.64,5079.85 6269.01,5079.85 6341.01,5151.85 U2.11
CAP4: U2.12 | length 967.3
  Top Layer w10: v2(6107.64,5564.85) 6149.64,5606.85
  Bottom Layer w10: v2(6107.64,5564.85) 6052.64,5509.85 6052.64,5128.48 6084.95,5096.16 6262.7,5096.16 6311.64,5145.1 6311.64,5272.85 6315.88,5277.09 U2.12@6338.19,5277.09
CAP5: U2.13 | length 1430.6
  Top Layer w10: v2(6607.64,5599.85) 6614.64,5606.85 6645.64,5606.85
  Bottom Layer w10: U2.13@6337.64,5293.09 6309.25,5293.09 6295.64,5279.48 6295.64,5151.73 6257.89,5113.98 6089.77,5113.98 6068.64,5135.1 6068.64,5503.22 6091.27,5525.85 6110.64,5525.85 6203.64,5618.85 6312.64,5618.85 6331.64,5599.85 v2(6607.64,5599.85)
CS_SIG: R14.2 U6.2 | length 1640.7
  Top Layer w10: v2(3613.64,3944.85) 3618.64,3949.85 3618.64,4004.85 3628.64,4014.85
  Bottom Layer w10: v1(3438.64,4059.85) v1(3833.64,4059.85) ; R14.2 3636.64,4351.87 v2(3636.64,4360.85) ; v2(3613.64,3944.85) 3858.64,3699.85 4533.64,3699.85 4583.64,3649.85 U6.2
  other v1: 3563.82,4058.64 3503.64,4059.85 3633.64,4059.85 3698.64,4059.85 3768.64,4059.85
D+: U1.24 U3.A6 U3.B6 | length 2936.4
  Bottom Layer w10: U3.A6@3404.54,5205.05 3373.84,5205.05 3353.64,5224.85 3353.64,5239.85 3358.14,5244.35 3404.54,5244.35 3414.54,5244.35 3416.36,5242.53 3673.59,5242.53 3979.64,4936.48 3979.64,4318.85 4101.64,4196.85 5130.64,4196.85 5233.91,4300.12 5233.91,4408.8 5225.18,4417.53 U1.24
D-: U1.23 U3.A7 U3.B7 | length 2973.4
  Bottom Layer w10: U3.B7@3404.54,5185.35 3453.64,5185.35 3453.44,5224.65 U3.A7@3404.54,5224.65 ; U3.A7@3404.54,5224.71 3414.54,5224.71 3416.36,5226.53 3666.96,5226.53 3963.64,4929.85 3963.64,4312.22 4095.01,4180.85 5137.27,4180.85 5249.91,4293.49 5249.91,4408.8 5258.64,4417.53 U1.23
D_SIG: R15.2 U6.3 | length 1606.2
  Bottom Layer w10: v1(4118.64,3949.85) v1(3653.64,3949.85) 3878.64,3724.85 4575.14,3724.85 4633.64,3666.35 U6.3
  other v1: 3852.74,3946 3922.96,3946.53 3723.64,3949.85 3788.64,3949.85 3983.64,3949.85 4053.64,3949.85
  other v2: 4118.64,3243.07
DS_SIG: R16.2 U6.4 | length 1143.4
  Top Layer w10: v2(4197.64,3921.85) 4197.64,3926.85 4181.64,3942.85 4181.64,3953.85 4196.64,3968.85 4196.64,3978.85 4185.64,3989.85 4185.64,3998.85 4198.64,4011.85
  Bottom Layer w10: v1(4008.64,4059.85) v1(4403.64,4059.85) ; v2(4197.64,3921.85) 4374.64,3744.85 4605.14,3744.85 4683.64,3666.35 U6.4
  other v1: 4073.64,4059.85 4138.64,4059.85 4203.64,4059.85 4268.64,4059.85 4338.64,4059.85
E0: U2.14 | length 4332.4
  Top Layer w8: 4616.27,5910.72 4620.68,5910.72 4654.94,5944.98 4654.94,5961.27 v2(4660.03,5966.35)
  Top Layer w10: 3072.72,5907.44 3107.06,5941.78 3577.61,5941.78 ; 3593.07,5898.85 3593.07,5926.33 3577.61,5941.78 ; 4101.39,5904 4063.61,5941.78 ; 4615.53,5901.27 4585,5901.27 4544.49,5941.78 4063.61,5941.78 ; 3577.61,5941.78 4063.61,5941.78
  Inner2 w8: v2@4657.48,5959.74 4674.78,5977.04 4821.84,5977.04 4892.57,5906.31 4966.6,5906.31 5004,5868.91 5026.14,5868.91 5042.16,5852.88 5042.16,5655.2 5048.7,5648.67 5327.08,5648.67 5501.1,5822.69 5530.18,5793.6 5531.54,5793.6 5585.88,5739.27 5585.88,5633.71 5484.51,5532.34 5484.51,5381.93 6064.89,5381.93 6098.07,5348.75 6142.08,5348.75 v2(6162.07,5328.76)
  Bottom Layer w8: v2@6162.3,5329.38 6170.89,5329.38 6192.15,5308.12 U2.14@6340.05,5308.12
E1: U2.15 | length 4593.6
  Top Layer w10: v2(4620.25,5982.35) 4628.85,5990.95 4697.26,5990.95 4719.65,5968.56 4719.65,5942.32 4688.1,5910.77 v2(4684.59,5910.77)
  Inner2 w8: v2@4619.91,5984.73 4626.23,5991.04 4827.64,5991.04 4898.37,5920.31 4972.4,5920.31 4978.8,5913.91 5001.03,5913.91 5017.43,5930.31 5030.43,5930.31 5056.16,5904.58 5056.16,5662.67 5321.28,5662.67 5501.1,5842.49 5535.98,5807.6 5537.34,5807.6 5599.88,5745.07 5599.88,5627.91 5498.51,5526.54 5498.51,5395.93 6070.69,5395.93 6103.61,5363.01 6181.42,5363.01 v2(6204.48,5339.96)
  Bottom Layer w8: v2@6210.92,5335.21 6222.79,5323.33 U2.15@6342.54,5323.33
  Bottom Layer w10: v2(3159.65,5913.72) 3184.78,5938.85 3647.99,5938.85 3673.99,5912.86 v2(3673.99,5909.77) 3737.41,5973.2 4128.05,5973.2 ; v2(4190.33,5910.91) 4128.05,5973.2 ; v2(4684.59,5910.77) 4674.91,5910.77 4624.13,5859.99 4574.59,5859.99 4564.59,5869.99 4564.59,5921.21 4512.6,5973.2 4128.05,5973.2
E2: U2.16 | length 4217
  Top Layer w10: 3253.35,5573.46 3337.14,5489.67 3680.73,5489.67 ; 3760.92,5569.85 3680.73,5489.67 ; 4272.68,5579.01 4183.34,5489.67 ; 4700.93,5491.13 4703.43,5491.13 ; 4785.59,5573.29 4703.43,5491.13 ; v2(5261.3,5688.86) 5063.57,5491.13 4703.43,5491.13 ; 3680.73,5489.67 4183.34,5489.67 ; 4183.34,5489.67 4701.97,5489.67 4703.43,5491.13
  Inner2 w10: v2@5264.35,5685.13 5271.81,5677.67 5315.06,5677.67 5501.1,5863.7 5542.19,5822.6 5543.55,5822.6 5614.88,5751.28 5614.88,5621.7 5513.51,5520.33 5513.51,5410.93 6076.9,5410.93 6109.82,5378.01 6187.63,5378.01 6196.18,5369.47 v2(6212.62,5369.47)
  Bottom Layer w8: v2@6214.65,5366.08 6217.37,5366.08 6235.68,5347.76 U2.16@6364.59,5347.76
E3: U2.17 | length 4230
  Top Layer w10: 4871.52,5898.06 4886.27,5912.82 4886.27,5953.01 4911.21,5977.95 v2(4958.53,5977.95)
  Inner2 w10: v2(3333.56,5909.72) 3396.65,5972.82 3739.79,5972.82 3770.52,5942.09 3854.31,5942.09 ; v2(3844.9,5909.85) 3844.9,5932.68 3854.31,5942.09 ; v2(4363.53,5909.85) 4331.29,5942.09 ; v2(4853.57,5909.91) 4832.78,5930.71 4725.2,5930.71 4715.7,5921.21 4715.7,5893.14 4701.74,5879.18 4681.9,5879.18 4661.29,5899.79 4584.2,5899.79 4541.9,5942.09 4331.29,5942.09 ; v2@4958.02,5978.46 4961.58,5982.02 5006.87,5982.02 5071.16,5917.72 5071.16,5677.67 5199.65,5677.67 5245,5723.02 5263.32,5723.02 5289.27,5697.07 5289.27,5693.67 5308.44,5693.67 5501.1,5886.33 5548.82,5838.6 5550.18,5838.6 5630.88,5757.91 5630.88,5615.07 5529.51,5513.7 5529.51,5426.93 6083.53,5426.93 6113.43,5397.03 6229.5,5397.03 v2(6235.01,5391.52) ; 3854.31,5942.09 4331.29,5942.09
  Bottom Layer w8: v2@6232.29,5386.77 6366.85,5386.77 6379.85,5373.76 U2.17@6379.85,5353.52
E4: U2.18 | length 4146.1
  Top Layer w10: 3418.02,5580.88 3458.09,5540.81 v2@3537.08,5540.81
  Inner2 w10: v2(3538.1,5539.79) 3756.39,5539.79 3760.97,5544.37 3907.52,5544.37 3931.94,5568.79 3931.94,5635.96 v2@3932.45,5636.47 ; 3920.59,5555.98 4426.63,5555.98 4445.93,5575.28 v2(4445.93,5638.5) ; v2@5092.1,5768.79 5087.16,5763.86 5087.16,5693.67 5193.02,5693.67 5238.38,5739.02 5269.95,5739.02 5299.3,5709.67 5301.81,5709.67 5501.1,5908.95 5555.44,5854.6 5556.81,5854.6 5646.88,5764.53 5646.88,5608.44 5545.51,5507.07 5545.51,5444.04 6034.9,5444.04 ; 6034.22,5443.36 6034.9,5444.04 ; v2(6373.07,5411.87) 6369.18,5415.77 6210.39,5415.77 6182.12,5444.04 6034.9,5444.04
  Bottom Layer w8: v2@6369.68,5407.12 6395.46,5381.34 U2.18@6395.46,5351.15
  Bottom Layer w10: v2(4445.93,5638.5) 4448,5636.44 4448,5606.69 4914.75,5606.69 v2(4963.01,5654.95) 5009.96,5607.99 5053.88,5607.99 5080.34,5634.45 5080.34,5758.16 v2(5094.36,5772.18)
  other v2: 3932.45,5637.49
E5: U2.19 | length 3543.5
  Top Layer w10: 4018.86,5574.42 4072.79,5520.49 v2@4097.22,5520.49 ; 5047.53,5733.18 5050.96,5729.74 5273.07,5729.74 5444.8,5558.01 v2(5658.89,5558.01)
  Inner2 w10: v2(3505.98,5616.52) 3505.98,5578.36 3517.43,5566.91 3606.3,5566.91 3617.42,5555.79 3749.77,5555.79 3754.35,5560.37 3900.89,5560.37 3905.16,5564.64 3905.16,5641.21 3912.03,5648.08 3912.03,5650.87 3922.8,5661.63 3942.49,5661.63 3957.94,5646.18 3957.94,5595.23 3947.94,5585.23 3947.94,5572.98 3948.95,5571.98 4007.16,5571.98 4018.89,5583.7 v2(4018.89,5618.81) ; v2(4098.24,5520.49) 4115.24,5537.49 4392.14,5537.49 4392.34,5537.28 4500.7,5537.28 4533.01,5569.58 4533.01,5646.93 v2@4534.02,5647.94 ; v2(5658.89,5558.01) 5704.82,5512.09 6309.83,5512.09 v2(6408.35,5413.57)
  Bottom Layer w8: v2@6403.6,5411.87 6410.39,5405.09 U2.19@6410.39,5361.67
  Bottom Layer w10: v2(4531.88,5583.37) 4717.35,5583.37 4741.01,5559.71 5006.96,5559.71 5038.17,5528.5 5060.56,5550.89 v2@5060.56,5567.85
  other v2: 5061.58,5566.15 4533.01,5649.3
E_SIG: R17.2 U6.5 | length 807.4
  Bottom Layer w10: v1(4228.64,3949.85) 4230,3948.49 v1(4692.49,3948.49) 4692.49,3697 4733.64,3655.85 U6.5
  other v1: 4628.39,3948.15 4293.64,3949.85 4358.64,3949.85 4423.64,3949.85 4493.64,3949.85 4558.64,3949.85
  other v2: 4688.55,3298.85
F0: U7.5
F1: U7.6
F2: U7.7
F3: U7.8
F_SIG: R18.2 U6.6 | length 799.7
  Bottom Layer w10: U6.6 4783.64,3637.85 4810.64,3664.85 4810.64,3946.85 v1(4813.64,3949.85) v1(5273.64,3949.85)
  other v1: 4878.64,3949.85 4943.64,3949.85 5008.64,3949.85 5073.64,3949.85 5143.64,3949.85 5208.64,3949.85
  other v2: 5273.64,3196.81
FS_SIG: R19.2 U6.7 | length 1265.4
  Top Layer w10: v2(5339.64,3946.85) 5356.64,3963.85 5356.64,3977.85 5343.64,3990.85 5343.64,4004.85 5351.64,4012.85
  Bottom Layer w10: U6.7 4833.64,3875.85 4867.64,3909.85 5302.64,3909.85 v2(5339.64,3946.85) ; v1(5163.64,4059.85) v1(5558.64,4059.85)
  other v1: 5228.64,4059.85 5293.64,4059.85 5358.64,4059.85 5428.64,4059.85 5488.64,4059.85
G_SIG: R20.2 U6.8 | length 1241
  Bottom Layer w10: U6.8 4883.64,3870.85 4897.64,3884.85 5318.64,3884.85 v1(5383.64,3949.85) v1(5843.64,3949.85)
  other v1: 5583.84,3946.23 5650.43,3948.27 5448.64,3949.85 5513.64,3949.85 5713.64,3949.85 5778.64,3949.85
  other v2: 5844.34,3247.85
GND: C1.1 C2.2 C3.1 C4.1 C5.1 C6.1 C7.2 C8.2 C9.2 C10.1 C11.1 C12.1 CN1.1 CN1.3 CN1.4 CN3.1 CN4.1 CN5.1 LED2.4 LED3.4 LED4.4 LED5.4 P1.1 P3.1 R1.1 R2.1 R6.1 R8.1 R9.1 R12.2 R14.1 R15.1 R16.1 R17.1 R18.1 R19.1 R20.1 R21.1 R22.1 R27.1 R28.1 R29.1 R30.1 SW1.2 SW2.1 U1.1 U1.2 U1.42 U1.43 U1.46 U1.47 U1.48 U1.49 U1.50 U1.51 U1.52 U1.53 U1.54 U1.55 U1.56 U1.57 U1.58 U1.59 U1.60 U1.GND U2.6 U3.12 U3.13 U3.14 U3.15 U3.A1B12 U3.A12B1 U4.2 U5.2 U6.9 U6.14 U7.9 U7.14 U8.5 U9.10 U10.1 U10.4 U10.5 | length 14576.1
  Top Layer w35: 3108.64,5164.85 5058.64,5164.85 ; v2(3108.64,5439.85) 5058.64,5439.85
  Bottom Layer w10: v2(3082.64,3948.85) 3082.64,3930.53 P3.1 ; CN1.1 3331.28,4554.22 3423.8,4461.7 CN1.3 3458.64,4348.12 3458.64,4244.85 3423.64,4209.85 ; U5.2 3241,4264.85 3251,4254.85 ; C9.2 3212.72,4858.21 U3.14 3212.72,5414.45 U3.13 3368.63,5376.78 3398.56,5346.85 3572.64,5346.85 3598.3,5321.19 R9.1 ; C10.1 3313.3,4064.85 R12.2 3303.64,4135.19 3303.64,4174.85 3258.64,4219.85 3258.64,4247.2 3251,4254.85 ; U4.2 3498.67,4764.82 ; R8.1 3522.33,5088.87 U3.A1B12 3404.57,5051.18 U3.12 3419.02,4964.85 3538.64,4964.85 3601.26,4902.23 3601.26,4769.85 ; C8.2 3686.2,4747.29 3663.64,4769.85 3601.26,4769.85 ; R15.1 4184.14,3251.01 v2(4184.14,3196.79) ; U10.5 U10.4 4539.83,5300.37 v2(4526.71,5300.37) 4511.2,5284.87 C11.1 4516.2,5214.85 C12.1 4562.7,5098.35 U9.10@4649.27,5098.35 ; U6.14 4633.64,3272.85 v2(4760.64,3145.85) 4883.64,3268.85 U6.9 ; U10.1 4677.64,5379.12 4677.64,5407.85 4693.64,5423.85 4754.64,5423.85 4777.3,5401.19 v2(4777.3,5391.85) ; v2(4768.64,3498.85) 4774.64,3504.85 5101.64,3504.85 5133.64,3472.85 U7.14 ; v2@4780.1,4374.27 4788.52,4365.85 R6.1 4987.66,4313.83 5038.64,4262.85 5077.2,4262.85 C6.1 ; C7.2 4905.22,4848.71 U1.42 U1.43 5125.97,4882.18 5158.25,4914.46 ; 4983.05,4990.45 U1.50@5158.25,4990.45 ; R19.1 5097.3,4078.98 5076.43,4099.86 3613.63,4099.86 3503.64,4209.85 ; U1.50 U1.50@5158.25,4990.45 ; 5258.64,4714.85 5193.68,4714.85 5193.68,4649.89 5258.64,4649.89 5323.6,4649.89 5323.6,4714.85 5323.6,4779.82 5258.64,4779.82 5193.68,4779.82 5193.68,4879.03 5158.25,4914.46 ; v2(5339.64,3200.85) 5383.64,3244.85 U7.9 ; U1.2 U1.1 5533.25,4989.47 U1.GND ; C4.1 5630.3,5124.07 R22.1 5566.9,4990.45 U1.GND ; C2.2 C5.1 5902.64,4931.29 v2(5902.64,5044.85) ; U2.6@6427.39,5238.21 6429.28,5238.21 v2(6440.64,5226.85) ; v2(6519.29,5182.73) 6532.17,5169.85 R1.1 ; C3.1 6579.2,5412.85 v2(6606.92,5385.13) ; R2.1 6788.64,5271.83 U8.5 6800.64,5199.66 v2(6800.64,5132.85) ; 3251,4254.85 3348.64,4254.85 3393.64,4209.85 3423.64,4209.85 ; 3423.64,4209.85 3503.64,4209.85 ; 3498.67,4764.82 3503.7,4769.85 3601.26,4769.85 ; 3498.67,4764.82 3508.64,4754.85 3508.64,4664.85 3490.53,4646.74 CN1.4 3533.64,4536.9 3533.64,4239.85 3503.64,4209.85 ; 5158.25,4914.46 U1.50@5158.25,4990.45 ; U1.50@5158.25,4990.45 U1.GND
  other v2: 5922.54,3119.84 6477.83,3148.85 3611.3,3197.85 5921.27,3221.84 6477.64,3796.85 7036.44,3862.58 4199.37,3871.85 4775.35,4370.88 5634.37,5053.85 3595.14,5159.85 6606.2,5294.85 3608.64,5314.85 3379.51,5514.35 3879.51,5514.35 4379.51,5514.35 4879.51,5514.35 5159.04,5855.79 6122.59,5855.79 5618.64,5864.85 5024.58,5903.73 4592.7,5932.22
GS_SIG: R22.2 U7.1 | length 1626.2
  Top Layer w10: v2(5691.26,5053.85) 5730.64,5014.47 5730.64,5004.85 ; v2(5908.64,3945.85) 5908.64,3957.85 5925.64,3974.85 5911.64,3988.85 5911.64,4002.85 5924.64,4015.85
  Bottom Layer w10: U7.1 5033.64,3739.85 5155.64,3861.85 5330.64,3861.85 5387.64,3918.85 5881.64,3918.85 v2(5908.64,3945.85) ; v1(5733.64,4059.85) v1(6128.64,4059.85)
  other v1: 5798.64,4059.85 5863.64,4059.85 5928.64,4059.85 5993.64,4059.85 6063.64,4059.85
MISO: U1.33 U6.12 U7.12 | length 2222.4
  Inner2 w10: v2(4762.89,4534.28) 4762.23,4534.28 4637.88,4409.92 4637.88,3995.05 4598.78,3955.96 4598.78,3934.92 4624.9,3908.8 4624.9,3633.48 4726.53,3531.85 v2(4771.64,3531.85)
  Bottom Layer w10: U6.12 4733.64,3528.85 4736.64,3531.85 v2(4771.64,3531.85) 5143.64,3531.85 5159.64,3515.85 5159.64,3361.85 5169.64,3351.85 5201.64,3351.85 5233.64,3383.85 U7.12 ; v2@4761.87,4535.8 4772.55,4546.49 U1.33@4986.77,4546.49
MOSI: U1.31 U6.11 U7.11 | length 2100.7
  Inner2 w10: v2(4764.88,4440.66) 4741.85,4417.62 4741.85,3628.37 4809.98,3560.24 4809.98,3411.18 v2(4770.64,3371.85)
  Bottom Layer w10: v2@4766.92,4441.17 4808.13,4482.38 U1.31@4988.26,4482.38 ; U6.11 4783.64,3448.85 4815.64,3480.85 5090.64,3480.85 5109.64,3461.85 5109.64,3357.85 5141.64,3325.85 5246.14,3325.85 5283.64,3363.35 U7.11
NEO: R32.2 U1.28 | length 2525.7
  Bottom Layer w10: R32.2 3725.61,5350.82 3690.64,5315.85 3690.64,5271.85 4025.64,4936.85 4025.64,4373.85 4068.64,4330.85 4932.64,4330.85 5021.64,4241.85 5116.64,4241.85 5158.64,4283.85 5158.64,4322.85 5091.32,4390.17 U1.28
NEO1: LED2.1 R32.1 | length 514.2
  Bottom Layer w10: LED2.1 3237.78,5486.72 3266.65,5457.85 3311.64,5457.85 3316.64,5462.85 3607.64,5462.85 3669.67,5400.82 R32.1
PWR: R34.2@6299.21,4343.12 R35.1 | length 78.4
  Bottom Layer w10: R34.2@6302.28,4337.82 6376.32,4337.82 R35.1@6379.37,4334.77
PWR_SENS: R31.2 U1.9 | length 74.3
  Bottom Layer w10: U1.9 5605.52,4681.39 R31.2
RST: C7.1 R7.2 SW1.1 U1.45 | length 1160.7
  Inner2 w10: v2@4733.61,5903.84 4817.88,5819.57 v2(4817.88,5056.63)
  Bottom Layer w10: v2(4817.88,5056.63) 4910.2,4964.31 R7.2@4910.2,4964.07 ; C7.1 R7.2@4910.2,4964.07 ; R7.2 R7.2@4910.2,4964.07 ; U1.45 4963.29,4949.11 4948.33,4964.07 R7.2@4910.2,4964.07
  other v2: 4739.62,5902.62
RX0: P2.1 U1.40 | length 2642.3
  Inner2 w8: v2(3081.66,3640.33) 3552.35,3640.33 3816.73,3904.71 3816.73,3940.67 3830.98,3954.91 3830.98,3956.5 3849.16,3974.67 3849.16,3988.92 3964.86,4104.63 4111.74,4104.63 4161.27,4154.15 4292.89,4154.15 4739.31,4600.57 4739.31,4749.24 v2(4767.88,4777.81)
  Bottom Layer w8: v2(3081.66,3640.33) 3081.66,3607.78 P2.1@3164.52,3524.92
  Bottom Layer w10: v2(4767.88,4777.81) 4771.85,4781.78 U1.40
RX1: P4.2 U1.22 | length 2940.8
  Inner2 w10: v2@7006.62,4275.82 7006.11,4275.82 6723.96,3993.67 6723.96,3975.35 6735.56,3963.76 6735.56,3957.65 6873.56,3819.65 6921.67,3819.65 6921.67,3545.88 6928.51,3539.04 6928.51,3529.61 7024.68,3433.44 v2(7037.66,3433.44)
  Bottom Layer w10: U1.22@5290.5,4437.14 5290.5,4405.93 5397,4299.44 7002.05,4299.44 7012.05,4289.44 v2(7012.05,4275.14)
RX2: R23.1 U1.34 U8.4 | length 2427.7
  Inner2 w8: v2(4777.53,4573.91) 4786.31,4582.68 5003.8,4582.68 5048.07,4538.41 5819.09,4538.41 6300.52,5019.84 6322.95,5019.84 6369.94,5066.83 6369.94,5089.26 6396.65,5115.97 6517.55,5115.97 v2(6525.55,5107.97)
  Bottom Layer w8: v2@4774.99,4573.4 4975.47,4573.4 U1.34@4985.14,4583.07
  Bottom Layer w10: R23.1 6577.15,5100.17 U8.4
SCK: U1.32 U6.13 U7.13 | length 2029.6
  Inner2 w10: v2@4756.43,4489.9 4719.68,4453.15 4719.68,4009 4668.12,3957.43 4668.12,3954.72 4658.99,3945.6 4658.99,3649.89 4647.59,3638.48 4724.22,3561.85 v2(4764.64,3561.85)
  Bottom Layer w10: U6.13 4683.64,3512.85 4732.64,3561.85 v2(4764.64,3561.85) 5144.64,3561.85 5183.64,3522.85 U7.13 ; v2(4761.93,4490.67) 4783.64,4512.38 U1.32@4979.38,4512.38
SCL: R4.2 U1.8 U2.2 U9.2 | length 5425.6
  Inner2 w10: v2(4659.32,5202.64) 4659.32,5078.16 4690.52,5046.96 4739.77,5046.96 4808.46,4978.27 5008.22,4978.27 5369.09,5339.14 5369.09,5369.82 5359.09,5379.82 5359.09,5614.21 5501.1,5756.22 5538.88,5718.44 5538.88,5653.18 5404.93,5519.23 5404.93,5297.69 5429.54,5273.08 5548.42,5273.08 5572.84,5248.65 5572.84,5172.33 5633.24,5111.93 6108.72,5111.93 6126.27,5094.38 6212.37,5094.38 6365.65,5247.66 6365.65,5310.76 6390.8,5335.91 6438.12,5335.91 6467.13,5364.91 6519.05,5364.91 6575.75,5308.22 6575.75,5239.49 6603.23,5212.02 v2@6608.96,5212.02 ; v2(6154.79,5028.19) 6235.35,5028.19 6404.32,5197.15 6498.2,5197.15 6531.83,5230.79 6531.83,5297.19 6512.46,5316.57 v2@6490.66,5316.57 ; 6478.31,5196.82 6479.72,5195.41 v2(6479.72,5168.6)
  Bottom Layer w10: v2(4659.32,5202.64) 4668.32,5211.64 U9.2@4668.32,5284.21 ; U1.8 5695.82,4714.85 5697.98,4717.01 5697.98,4850.56 ; R4.2 5697.98,4850.56 ; v2@6150.97,5023.44 5941.84,4814.31 5734.23,4814.31 5697.98,4850.56 ; U2.2@6457.79,5307.97 6476.48,5307.97 v2(6490.35,5321.84) ; v2(6479.72,5168.6) 6513.64,5134.67 6564.86,5134.67 6608.96,5178.77 v2(6608.96,5213.37)
SDA: R5.2 U1.7 U2.3 U9.3 | length 4349.8
  Inner2 w10: 4697.09,5063.02 v2(4697.09,5201.86) ; 4697.15,5062.96 4746.4,5062.96 4815.09,4994.27 5001.6,4994.27 5353.09,5345.76 5353.09,5363.19 5343.09,5373.19 5343.09,5620.84 5501.1,5778.85 5554.88,5725.06 5554.88,5646.55 5420.93,5512.6 5420.93,5304.32 5436.17,5289.08 5555.04,5289.08 5588.84,5255.28 5588.84,5178.96 5639.86,5127.93 5959,5127.93 v2@5992.7,5161.63 ; v2(6029.44,5029.8) 6108.02,5029.8 6134.35,5056.13 6237.65,5056.13 6410.59,5229.08 v2(6410.59,5292.69)
  Bottom Layer w10: U9.3@4687.7,5286.89 4687.7,5211.25 v2(4697.09,5201.86) ; U1.7 5616.05,4748.32 5632.98,4765.25 R5.2 5662.03,4905.9 5719.73,4905.9 5734.23,4891.4 5734.23,4859.34 5755.6,4837.97 5885.36,4837.97 6028.85,4981.46 6028.85,5013.17 ; v2(5993.04,5158.58) 5959.68,5125.22 5959.68,5057.27 6003.78,5013.17 6028.85,5013.17 ; v2@6028.85,5024.2 6028.85,5013.17 ; v2(6410.59,5292.69) U2.3@6438.94,5292.69
TX0: P2.2 U1.39 | length 2780.3
  Inner2 w8: v2@3090.33,3295.53 3236.99,3295.53 3915.64,3974.18 3915.64,4033.85 3971.64,4089.85 4119.64,4089.85 4164.64,4134.85 4299.32,4134.85 4756.16,4591.69 4756.16,4718.76 4768.88,4731.48 v2(4768.88,4732.49)
  Bottom Layer w8: v2(3086.6,3295.53) 3086.6,3331.49 P2.2@3183.86,3428.75
  Bottom Layer w10: v2@4768.37,4730.46 4786.23,4748.32 U1.39
TX1: P4.1 U1.21 | length 2793.1
  Inner2 w10: v2@7024.68,3525.79 6964.39,3525.79 6937.67,3552.51 6937.67,3827.28 6798.76,3966.19 6798.76,3995.2 7035.2,4231.64 7035.2,4312.88 v2(7030.79,4317.29)
  Bottom Layer w10: U1.21@5323.28,4439.81 5323.28,4419.06 5369.06,4373.28 6978.14,4373.28 v2@7033.53,4317.89
  other v2: 7029.26,3526.56
TX2: R26.2 U1.35 | length 1806
  Inner2 w8: v2(4782.11,4623.26) 5137.78,4623.26 5384.09,4869.57 5384.09,5495.54 5376.09,5503.54 5376.09,5582.85 v2@5497.43,5704.19
  Bottom Layer w8: v2@4782.62,4623.77 4796.36,4610.03 U1.35@4990.73,4610.03
  other v2: 5493.95,5703.33
VCC: R34.2@6752.83,3809.1 R35.2 | length 7936.7
  Bottom Layer w10: v1(3118.64,3974.85) 3118.98,3974.51 v1(4584.23,3974.51) 6948.3,3974.51 v1(6948.64,3974.85) 6995.64,3974.85 7018.64,3951.85 6991.64,3924.85 6975.64,3924.85 6930.64,3879.85 6930.64,3799.51 6874.98,3743.85 6820.48,3743.85 R34.2@6759.96,3804.37 ; v1(3383.64,3974.85) 3403.64,3994.85 v1(3403.64,4034.85) 3404.09,4034.4 v1(3607.56,4034.4) 6663.19,4034.4 v1(6663.64,4034.85) ; v1(6268.64,4034.85) 6268.64,4103.51 6388.15,4223.02 R35.2@6388.15,4266.65
  other v1: 3576.53,3973.04 4650.59,3973.15 6690.9,3973.49 6757.54,3973.34 6824.52,3973.79 3183.64,3974.85 3248.64,3974.85 3313.64,3974.85 3448.64,3974.85 3513.64,3974.85 3688.64,3974.85 3753.64,3974.85 3953.64,3974.85 4018.64,3974.85 4083.64,3974.85 4153.64,3974.85 4258.64,3974.85 4323.64,3974.85 4388.64,3974.85 4453.64,3974.85 4523.64,3974.85 4718.64,3974.85 4843.64,3974.85 4908.64,3974.85 4973.64,3974.85 5043.64,3974.85 5108.64,3974.85 5173.64,3974.85 5238.64,3974.85 5308.64,3974.85 5413.64,3974.85 5478.64,3974.85 5541.61,3974.62 5678.64,3974.85 5743.64,3974.85 5808.64,3974.85 5878.64,3974.85 5983.64,3974.85 6048.64,3974.85 6113.64,3974.85 6178.64,3974.85 6248.64,3974.85 6313.64,3974.85 6378.64,3974.85 6443.64,3974.85 6553.64,3974.85 6618.64,3974.85 6883.64,3974.85 5609.8,3975.53 3887.86,3978.07 3821.81,3979.15 3468.64,4034.85 3538.64,4034.85 3668.64,4034.85 3733.64,4034.85 3798.64,4034.85 3973.64,4034.85 4038.64,4034.85 4103.64,4034.85 4173.64,4034.85 4243.64,4034.85 4303.64,4034.85 4368.64,4034.85 5128.64,4034.85 5193.64,4034.85 5258.64,4034.85 5328.64,4034.85 5393.64,4034.85 5463.64,4034.85 5528.64,4034.85 5698.64,4034.85 5763.64,4034.85 5833.64,4034.85 5898.64,4034.85 5963.64,4034.85 6028.64,4034.85 6093.64,4034.85 6338.64,4034.85 6403.64,4034.85 6468.64,4034.85 6533.64,4034.85 6598.64,4034.85
VUSB: D1.2 LED1.1 Q1.1 R11.2 U3.A4B9 U3.A9B4 U5.4 U10.6 | length 3332
  Bottom Layer w10: LED1.1 3098.64,4246.38 3098.64,4499.85 ; R11.2 3368.98,4869.85 3288.64,4869.85 3273.64,4854.85 ; U3.A4B9 3368.13,5120.36 3348.64,5139.85 ; Q1.1 3383.04,4302.25 U5.4 3304.06,4504.43 3298.64,4509.85 3108.64,4509.85 3098.64,4499.85 ; U10.6 4618.8,5425.69 4607.64,5436.85 3760.64,5436.85 3652.64,5328.85 3652.64,5300.85 3614.64,5262.85 3583.64,5262.85 3566.64,5279.85 3566.64,5321.85 3557.64,5330.85 3467.64,5330.85 3444.64,5307.85 3406.06,5307.85 U3.A9B4 3404.06,5309.85 3373.64,5309.85 3346.83,5283.04 3346.83,5255.66 3337.64,5246.48 3337.64,5218.13 3348.64,5207.35 3348.64,5139.85 ; 3098.64,4499.85 3098.64,4575.87 D1.2 3273.64,4750.87 3273.64,4854.85 ; 3273.64,4854.85 3273.64,5064.85 3348.64,5139.85
"": CN2.1 CN2.2 CN2.5 CN3.2 CN3.5 CN4.2 CN4.3 CN4.5 CN5.2 CN5.3 CN5.5 LED5.3 P1.3 P1.4 P2.3 P2.4 P3.3 P3.4 P4.3 P4.4 Q1.2 SW1.3 SW1.4 SW2.3 SW2.4 U1.5 U1.6 U1.10 U1.11 U1.12 U1.13 U1.16 U1.17 U1.18 U1.19 U1.20 U1.25 U1.26 U1.27 U1.30 U1.36 U1.37 U1.38 U1.41 U1.44 U1.61 U1.62 U1.63 U1.64 U1.65 U1.66 U1.67 U1.68 U1.69 U1.70 U1.71 U1.72 U3.A8 U3.B8 U4.4 U8.3 U9.5 U9.8 U9.9 | length 3903.8
  Top Layer w10: 3108.64,5194.85 5058.64,5234.85 ; 3108.64,5409.85 5058.64,5294.85

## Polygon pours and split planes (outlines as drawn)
GND on Inner1 (split plane): 3158.64,3020.95 cw(c3111.69,3067.9) 3064.74,3114.85 3064.74,5914.85 cw(c3111.69,5961.8) 3158.64,6008.75 6958.64,6008.75 cw(c7005.59,5961.8) 7052.54,5914.85 7052.54,3114.85 cw(c7005.59,3067.9) 6958.64,3020.95 3158.64,3020.95

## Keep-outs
Inner1:
  region net "": 3061.31,5565.03 5061.82,5565.03 5061.82,5880.87 3061.31,5880.87
Board Outline Layer:
  lines w10 net "": 3058.64,3114.85 ccw(c3158.64,3114.85) 3158.64,3014.85 6958.64,3014.85 ccw(c6958.64,3114.85) 7058.64,3114.85 7058.64,5914.85 ccw(c6958.64,5914.85) 6958.64,6014.85 3158.64,6014.85 ccw(c3158.64,5914.85) 3058.64,5914.85 3058.64,3114.85

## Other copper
Top Layer:
  drawing of 256 lines, arcs and shapes, not listed

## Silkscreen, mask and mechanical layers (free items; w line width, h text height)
Top Solder Mask Layer:
  drawing of 240 lines, arcs and shapes, not listed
